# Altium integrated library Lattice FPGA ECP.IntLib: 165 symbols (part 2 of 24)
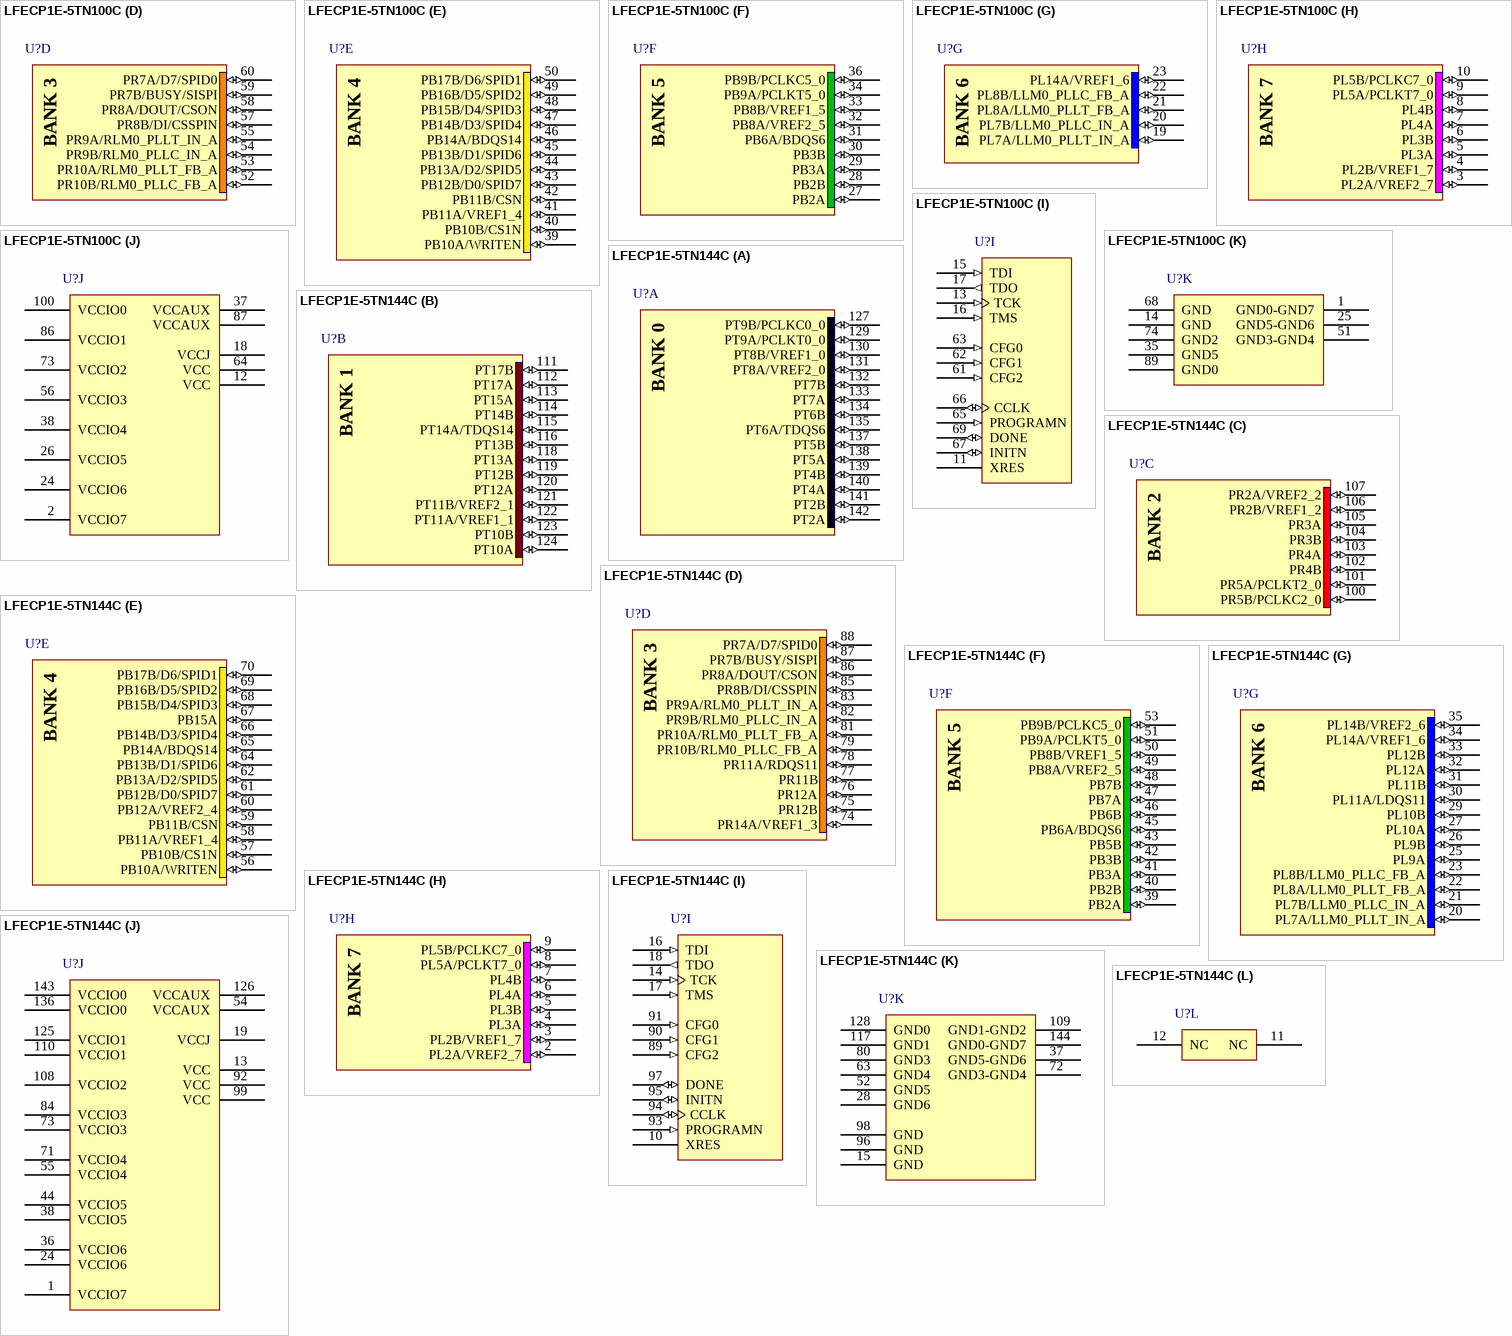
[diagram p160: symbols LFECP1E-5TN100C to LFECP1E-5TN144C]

## LFECP1E-5TN144C
designator U?
ECP 1.2V FPGA, 97 I/Os, 2 PLLs, 1.5K LUTs, 144-Pin TQFP, Pb-Free, Speed Grade 5, Commercial Temperature Grade; Note: Pins 37, 72, 109 and 144 are double bonded.; ComponentAvailability: Not Available
footprint TQFP144_N (Thin QFP, 144-Leads, Body 20x20mm, Pitch 0.5mm, IPC Medium Density)
footprint TQFP144_L (Thin QFP, 144-Leads, Body 20x20mm, Pitch 0.5mm, IPC High Density)
footprint TQFP144_M (Thin QFP, 144-Leads, Body 20x20mm, Pitch 0.5mm, IPC Low Density)
3D model ECP1E-TQFP-144 (144-Pin Thin Quad Flat Pack (TQFP144))
part A pins: 127 PT9B/PCLKC0_0 (io), 129 PT9A/PCLKT0_0 (io), 130 PT8B/VREF1_0 (io), 131 PT8A/VREF2_0 (io), 132 PT7B (io), 133 PT7A (io), 134 PT6B (io), 135 PT6A/TDQS6 (io), 137 PT5B (io), 138 PT5A (io), 139 PT4B (io), 140 PT4A (io), 141 PT2B (io), 142 PT2A (io)
part B pins: 111 PT17B (io), 112 PT17A (io), 113 PT15A (io), 114 PT14B (io), 115 PT14A/TDQS14 (io), 116 PT13B (io), 118 PT13A (io), 119 PT12B (io), 120 PT12A (io), 121 PT11B/VREF2_1 (io), 122 PT11A/VREF1_1 (io), 123 PT10B (io), 124 PT10A (io)
part C pins: 100 PR5B/PCLKC2_0 (io), 101 PR5A/PCLKT2_0 (io), 102 PR4B (io), 103 PR4A (io), 104 PR3B (io), 105 PR3A (io), 106 PR2B/VREF1_2 (io), 107 PR2A/VREF2_2 (io)
part D pins: 74 PR14A/VREF1_3 (io), 75 PR12B (io), 76 PR12A (io), 77 PR11B (io), 78 PR11A/RDQS11 (io), 79 PR10B/RLM0_PLLC_FB_A (io), 81 PR10A/RLM0_PLLT_FB_A (io), 82 PR9B/RLM0_PLLC_IN_A (io), 83 PR9A/RLM0_PLLT_IN_A (io), 85 PR8B/DI/CSSPIN (io), 86 PR8A/DOUT/CSON (io), 87 PR7B/BUSY/SISPI (io), 88 PR7A/D7/SPID0 (io)
part E pins: 56 PB10A/WRITEN (io), 57 PB10B/CS1N (io), 58 PB11A/VREF1_4 (io), 59 PB11B/CSN (io), 60 PB12A/VREF2_4 (io), 61 PB12B/D0/SPID7 (io), 62 PB13A/D2/SPID5 (io), 64 PB13B/D1/SPID6 (io), 65 PB14A/BDQS14 (io), 66 PB14B/D3/SPID4 (io), 67 PB15A (io), 68 PB15B/D4/SPID3 (io), 69 PB16B/D5/SPID2 (io), 70 PB17B/D6/SPID1 (io)
part F pins: 39 PB2A (io), 40 PB2B (io), 41 PB3A (io), 42 PB3B (io), 43 PB5B (io), 45 PB6A/BDQS6 (io), 46 PB6B (io), 47 PB7A (io), 48 PB7B (io), 49 PB8A/VREF2_5 (io), 50 PB8B/VREF1_5 (io), 51 PB9A/PCLKT5_0 (io), 53 PB9B/PCLKC5_0 (io)
part G pins: 20 PL7A/LLM0_PLLT_IN_A (io), 21 PL7B/LLM0_PLLC_IN_A (io), 22 PL8A/LLM0_PLLT_FB_A (io), 23 PL8B/LLM0_PLLC_FB_A (io), 25 PL9A (io), 26 PL9B (io), 27 PL10A (io), 29 PL10B (io), 30 PL11A/LDQS11 (io), 31 PL11B (io), 32 PL12A (io), 33 PL12B (io), 34 PL14A/VREF1_6 (io), 35 PL14B/VREF2_6 (io)
part H pins: 2 PL2A/VREF2_7 (io), 3 PL2B/VREF1_7 (io), 4 PL3A (io), 5 PL3B (io), 6 PL4A (io), 7 PL4B (io), 8 PL5A/PCLKT7_0 (io), 9 PL5B/PCLKC7_0 (io)
part I pins: 10 XRES, 14 TCK (in), 16 TDI (in), 17 TMS (in), 18 TDO (out), 89 CFG2 (in), 90 CFG1 (in), 91 CFG0 (in), 93 PROGRAMN (in), 94 CCLK (io), 95 INITN (io), 97 DONE (io)
part J pins: 1 VCCIO7 (power), 13 VCC (power), 19 VCCJ (power), 24 VCCIO6 (power), 36 VCCIO6 (power), 38 VCCIO5 (power), 44 VCCIO5 (power), 54 VCCAUX (power), 55 VCCIO4 (power), 71 VCCIO4 (power), 73 VCCIO3 (power), 84 VCCIO3 (power), 92 VCC (power), 99 VCC (power), 108 VCCIO2 (power), 110 VCCIO1 (power), 125 VCCIO1 (power), 126 VCCAUX (power), 136 VCCIO0 (power), 143 VCCIO0 (power)
part K pins: 15 GND (power), 28 GND6 (power), 37 GND5-GND6 (power), 52 GND5 (power), 63 GND4 (power), 72 GND3-GND4 (power), 80 GND3 (power), 96 GND (power), 98 GND (power), 109 GND1-GND2 (power), 117 GND1 (power), 128 GND0 (power), 144 GND0-GND7 (power)
part L pins: 11 NC, 12 NC

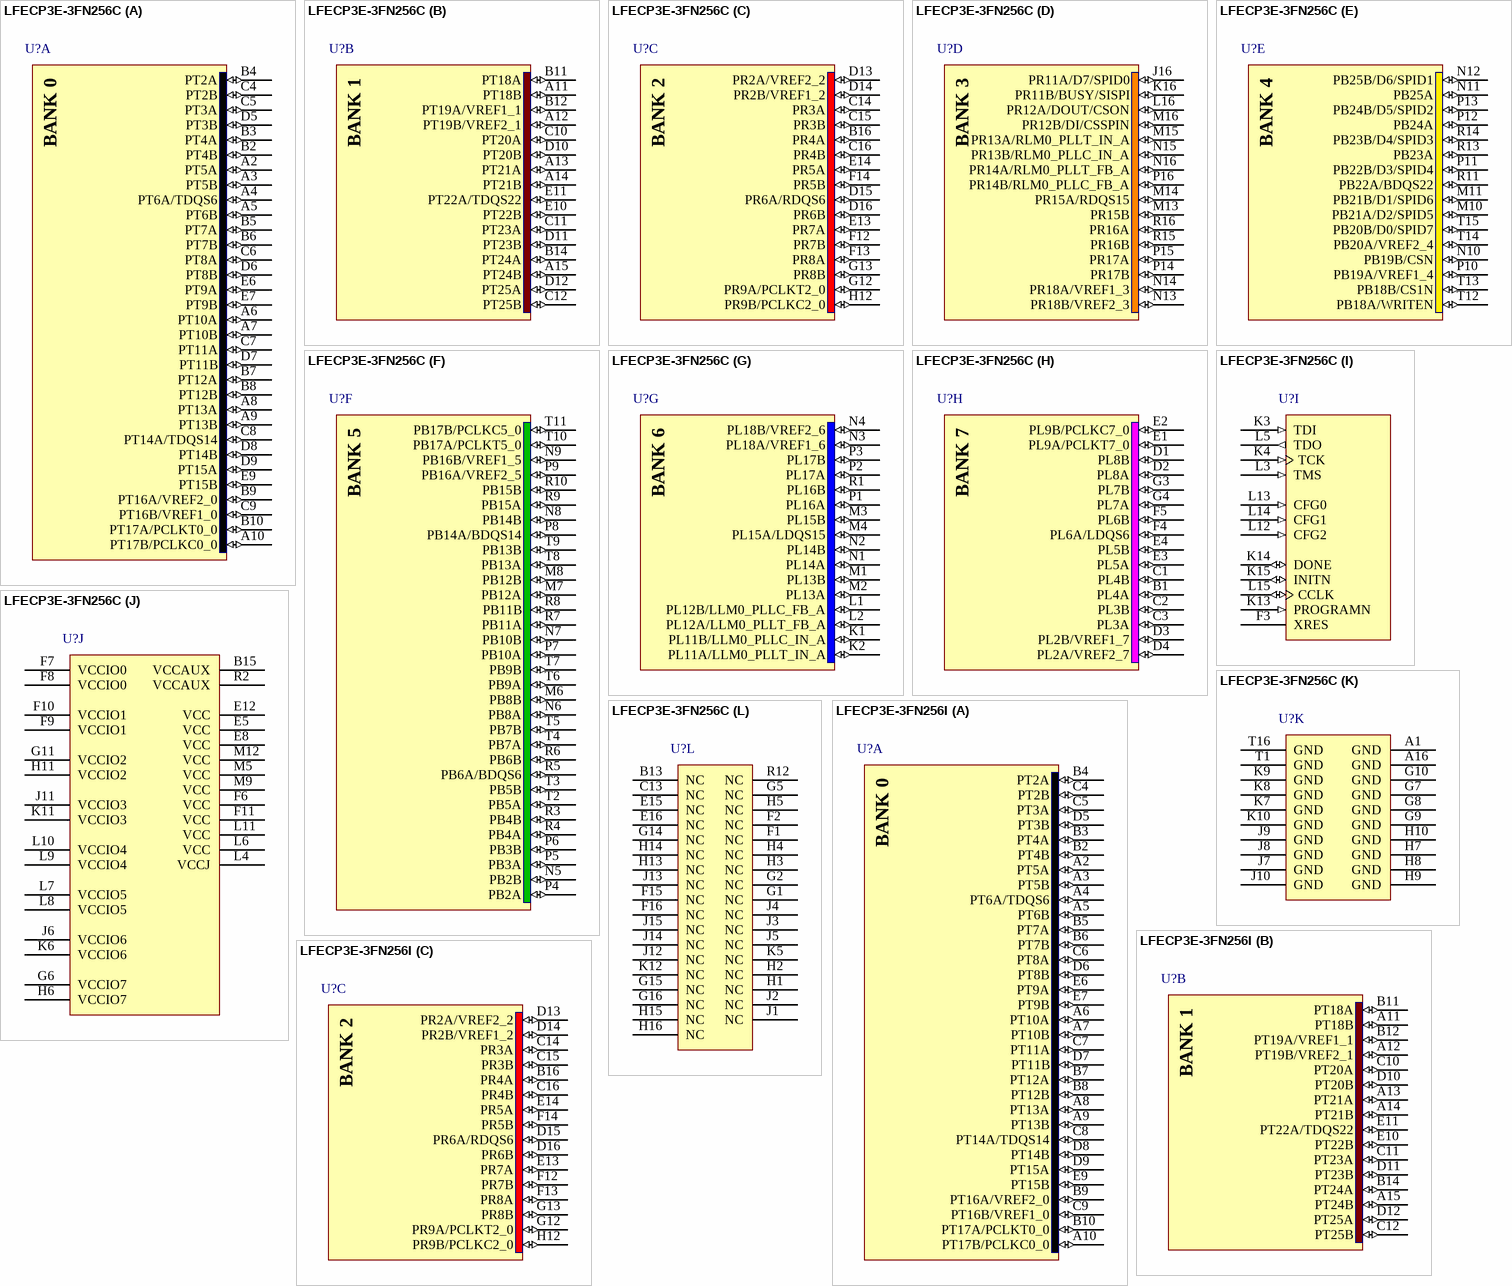
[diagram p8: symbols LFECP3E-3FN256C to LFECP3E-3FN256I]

## LFECP3E-3FN256C
designator U?
ECP 1.2V FPGA, 160 I/Os, 2 PLLs, 3.1K LUTs, 256-Pin fpBGA, Pb-Free, Speed Grade 3, Commercial Temperature Grade; ComponentAvailability: Not Available
footprint fpBGA256 (BGA, 256-Leads, Body 17x17mm, Pitch 1mm)
3D model ECP3E-fpBGA256 (256-Ball Fine Pitch Ball Grid Array (fpBGA256))
part A pins: A2 PT5A (io), A3 PT5B (io), A4 PT6A/TDQS6 (io), A5 PT6B (io), A6 PT10A (io), A7 PT10B (io), A8 PT13A (io), A9 PT13B (io), A10 PT17B/PCLKC0_0 (io), B2 PT4B (io), B3 PT4A (io), B4 PT2A (io), B5 PT7A (io), B6 PT7B (io), B7 PT12A (io), B8 PT12B (io), B9 PT16A/VREF2_0 (io), B10 PT17A/PCLKT0_0 (io), C4 PT2B (io), C5 PT3A (io), C6 PT8A (io), C7 PT11A (io), C8 PT14A/TDQS14 (io), C9 PT16B/VREF1_0 (io), D5 PT3B (io), D6 PT8B (io), D7 PT11B (io), D8 PT14B (io), D9 PT15A (io), E6 PT9A (io), E7 PT9B (io), E9 PT15B (io)
part B pins: A11 PT18B (io), A12 PT19B/VREF2_1 (io), A13 PT21A (io), A14 PT21B (io), A15 PT24B (io), B11 PT18A (io), B12 PT19A/VREF1_1 (io), B14 PT24A (io), C10 PT20A (io), C11 PT23A (io), C12 PT25B (io), D10 PT20B (io), D11 PT23B (io), D12 PT25A (io), E10 PT22B (io), E11 PT22A/TDQS22 (io)
part C pins: B16 PR4A (io), C14 PR3A (io), C15 PR3B (io), C16 PR4B (io), D13 PR2A/VREF2_2 (io), D14 PR2B/VREF1_2 (io), D15 PR6A/RDQS6 (io), D16 PR6B (io), E13 PR7A (io), E14 PR5A (io), F12 PR7B (io), F13 PR8A (io), F14 PR5B (io), G12 PR9A/PCLKT2_0 (io), G13 PR8B (io), H12 PR9B/PCLKC2_0 (io)
part D pins: J16 PR11A/D7/SPID0 (io), K16 PR11B/BUSY/SISPI (io), L16 PR12A/DOUT/CSON (io), M13 PR15B (io), M14 PR15A/RDQS15 (io), M15 PR13A/RLM0_PLLT_IN_A (io), M16 PR12B/DI/CSSPIN (io), N13 PR18B/VREF2_3 (io), N14 PR18A/VREF1_3 (io), N15 PR13B/RLM0_PLLC_IN_A (io), N16 PR14A/RLM0_PLLT_FB_A (io), P14 PR17B (io), P15 PR17A (io), P16 PR14B/RLM0_PLLC_FB_A (io), R15 PR16B (io), R16 PR16A (io)
part E pins: M10 PB21A/D2/SPID5 (io), M11 PB21B/D1/SPID6 (io), N10 PB19B/CSN (io), N11 PB25A (io), N12 PB25B/D6/SPID1 (io), P10 PB19A/VREF1_4 (io), P11 PB22B/D3/SPID4 (io), P12 PB24A (io), P13 PB24B/D5/SPID2 (io), R11 PB22A/BDQS22 (io), R13 PB23A (io), R14 PB23B/D4/SPID3 (io), T12 PB18A/WRITEN (io), T13 PB18B/CS1N (io), T14 PB20A/VREF2_4 (io), T15 PB20B/D0/SPID7 (io)
part F pins: M6 PB8B (io), M7 PB12A (io), M8 PB12B (io), N5 PB2B (io), N6 PB8A (io), N7 PB10B (io), N8 PB14B (io), N9 PB16B/VREF1_5 (io), P4 PB2A (io), P5 PB3A (io), P6 PB3B (io), P7 PB10A (io), P8 PB14A/BDQS14 (io), P9 PB16A/VREF2_5 (io), R3 PB4B (io), R4 PB4A (io), R5 PB6A/BDQS6 (io), R6 PB6B (io), R7 PB11A (io), R8 PB11B (io), R9 PB15A (io), R10 PB15B (io), T2 PB5A (io), T3 PB5B (io), T4 PB7A (io), T5 PB7B (io), T6 PB9A (io), T7 PB9B (io), T8 PB13A (io), T9 PB13B (io), T10 PB17A/PCLKT5_0 (io), T11 PB17B/PCLKC5_0 (io)
part G pins: K1 PL11B/LLM0_PLLC_IN_A (io), K2 PL11A/LLM0_PLLT_IN_A (io), L1 PL12B/LLM0_PLLC_FB_A (io), L2 PL12A/LLM0_PLLT_FB_A (io), M1 PL13B (io), M2 PL13A (io), M3 PL15B (io), M4 PL15A/LDQS15 (io), N1 PL14A (io), N2 PL14B (io), N3 PL18A/VREF1_6 (io), N4 PL18B/VREF2_6 (io), P1 PL16A (io), P2 PL17A (io), P3 PL17B (io), R1 PL16B (io)
part H pins: B1 PL4A (io), C1 PL4B (io), C2 PL3B (io), C3 PL3A (io), D1 PL8B (io), D2 PL8A (io), D3 PL2B/VREF1_7 (io), D4 PL2A/VREF2_7 (io), E1 PL9A/PCLKT7_0 (io), E2 PL9B/PCLKC7_0 (io), E3 PL5A (io), E4 PL5B (io), F4 PL6A/LDQS6 (io), F5 PL6B (io), G3 PL7B (io), G4 PL7A (io)
part I pins: F3 XRES, K3 TDI (in), K4 TCK (in), K13 PROGRAMN (in), K14 DONE (io), K15 INITN (io), L3 TMS (in), L5 TDO (out), L12 CFG2 (in), L13 CFG0 (in), L14 CFG1 (in), L15 CCLK (io)
part J pins: B15 VCCAUX (power), E5 VCC (power), E8 VCC (power), E12 VCC (power), F6 VCC (power), F7 VCCIO0 (power), F8 VCCIO0 (power), F9 VCCIO1 (power), F10 VCCIO1 (power), F11 VCC (power), G6 VCCIO7 (power), G11 VCCIO2 (power), H6 VCCIO7 (power), H11 VCCIO2 (power), J6 VCCIO6 (power), J11 VCCIO3 (power), K6 VCCIO6 (power), K11 VCCIO3 (power), L4 VCCJ (power), L6 VCC (power), L7 VCCIO5 (power), L8 VCCIO5 (power), L9 VCCIO4 (power), L10 VCCIO4 (power), L11 VCC (power), M5 VCC (power), M9 VCC (power), M12 VCC (power), R2 VCCAUX (power)
part K pins: A1 GND (power), A16 GND (power), G7 GND (power), G8 GND (power), G9 GND (power), G10 GND (power), H7 GND (power), H8 GND (power), H9 GND (power), H10 GND (power), J7 GND (power), J8 GND (power), J9 GND (power), J10 GND (power), K7 GND (power), K8 GND (power), K9 GND (power), K10 GND (power), T1 GND (power), T16 GND (power)
part L pins: B13 NC, C13 NC, E15 NC, E16 NC, F1 NC, F2 NC, F15 NC, F16 NC, G1 NC, G2 NC, G5 NC, G14 NC, G15 NC, G16 NC, H1 NC, H2 NC, H3 NC, H4 NC, H5 NC, H13 NC, H14 NC, H15 NC, H16 NC, J1 NC, J2 NC, J3 NC, J4 NC, J5 NC, J12 NC, J13 NC, J14 NC, J15 NC, K5 NC, K12 NC, R12 NC

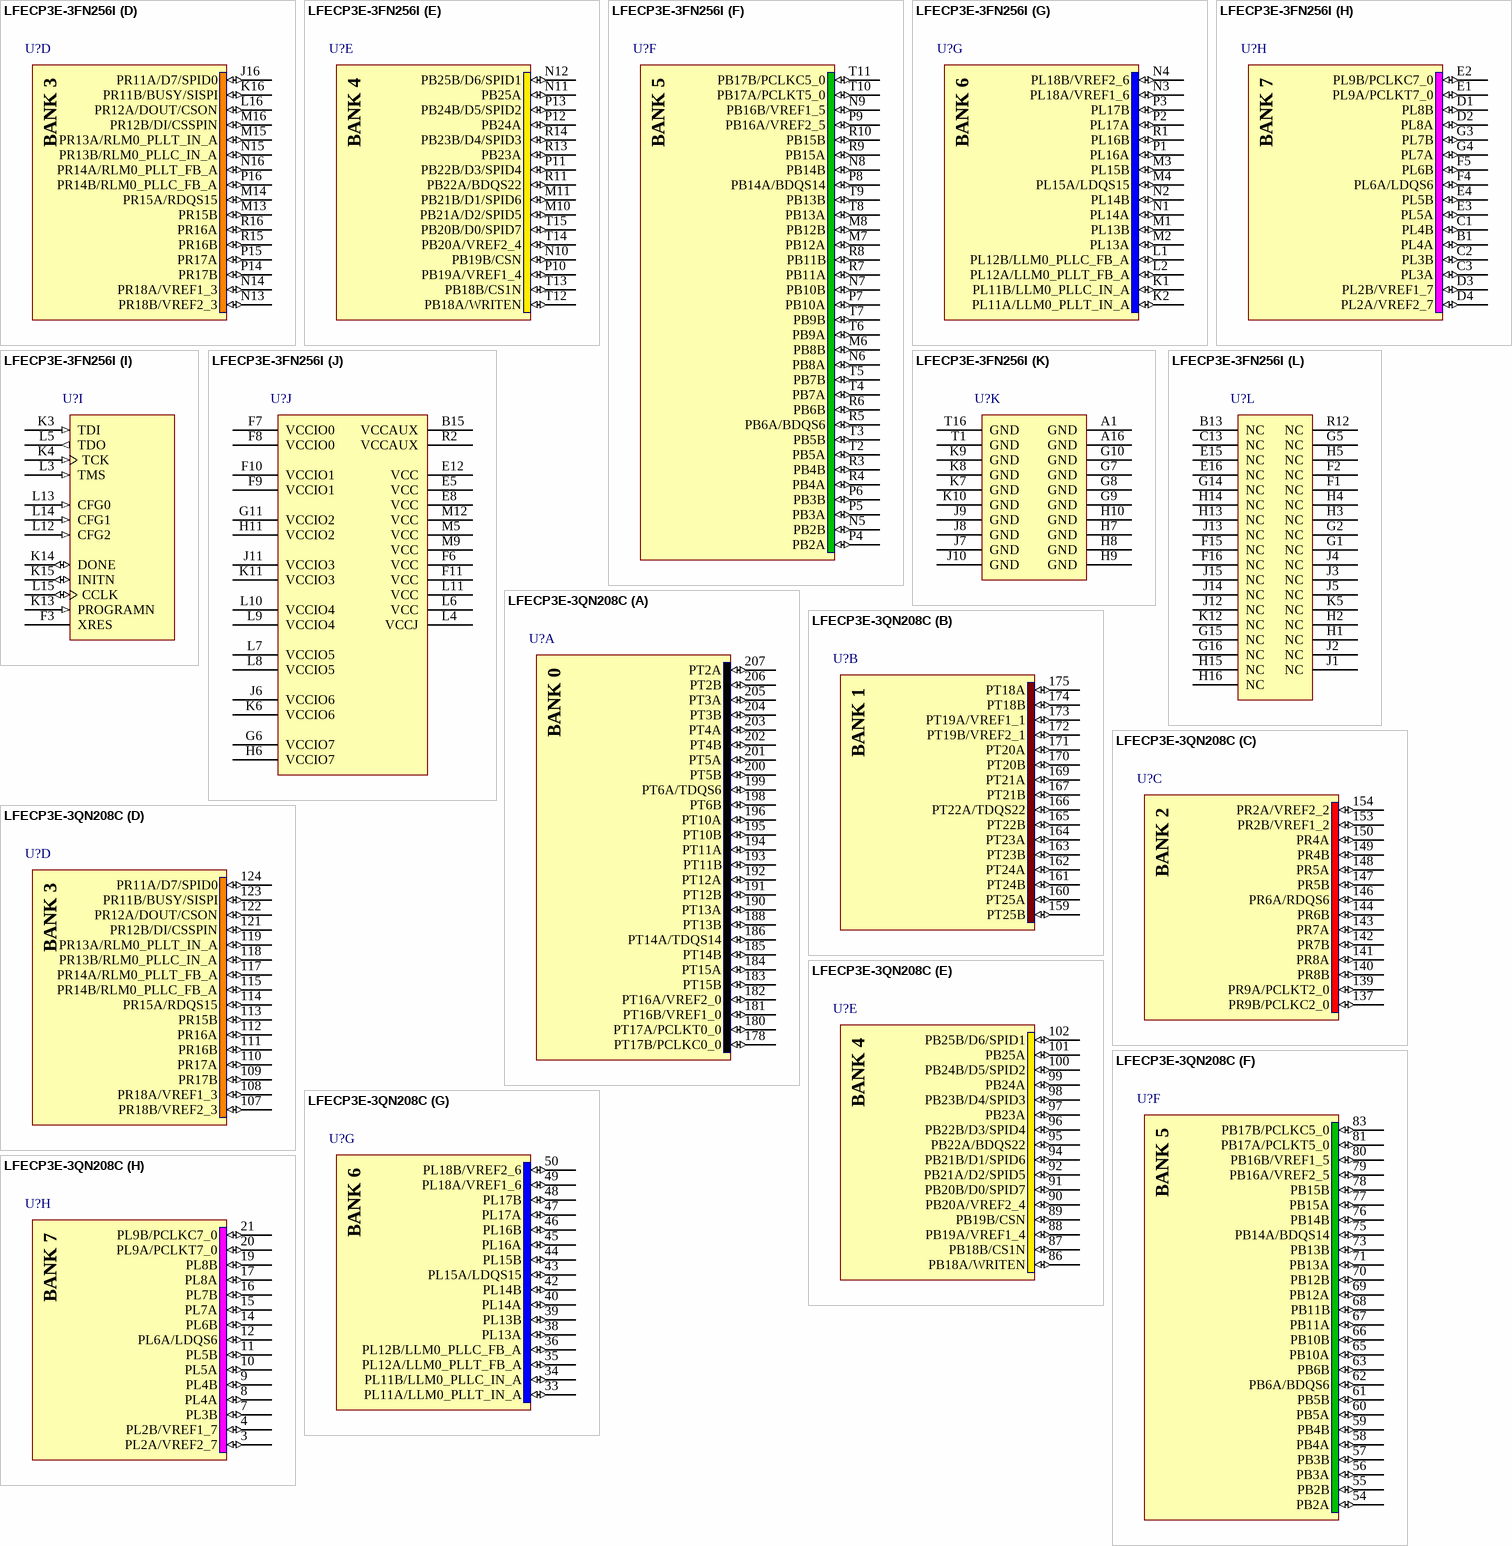
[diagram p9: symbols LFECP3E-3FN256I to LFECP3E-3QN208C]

## LFECP3E-3FN256I
designator U?
ECP 1.2V FPGA, 160 I/Os, 2 PLLs, 3.1K LUTs, 256-Pin fpBGA, Pb-Free, Speed Grade 3, Industrial Temperature Grade; ComponentAvailability: Not Available
footprint fpBGA256 (BGA, 256-Leads, Body 17x17mm, Pitch 1mm)
3D model ECP3E-fpBGA256 (256-Ball Fine Pitch Ball Grid Array (fpBGA256))
part A pins: A2 PT5A (io), A3 PT5B (io), A4 PT6A/TDQS6 (io), A5 PT6B (io), A6 PT10A (io), A7 PT10B (io), A8 PT13A (io), A9 PT13B (io), A10 PT17B/PCLKC0_0 (io), B2 PT4B (io), B3 PT4A (io), B4 PT2A (io), B5 PT7A (io), B6 PT7B (io), B7 PT12A (io), B8 PT12B (io), B9 PT16A/VREF2_0 (io), B10 PT17A/PCLKT0_0 (io), C4 PT2B (io), C5 PT3A (io), C6 PT8A (io), C7 PT11A (io), C8 PT14A/TDQS14 (io), C9 PT16B/VREF1_0 (io), D5 PT3B (io), D6 PT8B (io), D7 PT11B (io), D8 PT14B (io), D9 PT15A (io), E6 PT9A (io), E7 PT9B (io), E9 PT15B (io)
part B pins: A11 PT18B (io), A12 PT19B/VREF2_1 (io), A13 PT21A (io), A14 PT21B (io), A15 PT24B (io), B11 PT18A (io), B12 PT19A/VREF1_1 (io), B14 PT24A (io), C10 PT20A (io), C11 PT23A (io), C12 PT25B (io), D10 PT20B (io), D11 PT23B (io), D12 PT25A (io), E10 PT22B (io), E11 PT22A/TDQS22 (io)
part C pins: B16 PR4A (io), C14 PR3A (io), C15 PR3B (io), C16 PR4B (io), D13 PR2A/VREF2_2 (io), D14 PR2B/VREF1_2 (io), D15 PR6A/RDQS6 (io), D16 PR6B (io), E13 PR7A (io), E14 PR5A (io), F12 PR7B (io), F13 PR8A (io), F14 PR5B (io), G12 PR9A/PCLKT2_0 (io), G13 PR8B (io), H12 PR9B/PCLKC2_0 (io)
part D pins: J16 PR11A/D7/SPID0 (io), K16 PR11B/BUSY/SISPI (io), L16 PR12A/DOUT/CSON (io), M13 PR15B (io), M14 PR15A/RDQS15 (io), M15 PR13A/RLM0_PLLT_IN_A (io), M16 PR12B/DI/CSSPIN (io), N13 PR18B/VREF2_3 (io), N14 PR18A/VREF1_3 (io), N15 PR13B/RLM0_PLLC_IN_A (io), N16 PR14A/RLM0_PLLT_FB_A (io), P14 PR17B (io), P15 PR17A (io), P16 PR14B/RLM0_PLLC_FB_A (io), R15 PR16B (io), R16 PR16A (io)
part E pins: M10 PB21A/D2/SPID5 (io), M11 PB21B/D1/SPID6 (io), N10 PB19B/CSN (io), N11 PB25A (io), N12 PB25B/D6/SPID1 (io), P10 PB19A/VREF1_4 (io), P11 PB22B/D3/SPID4 (io), P12 PB24A (io), P13 PB24B/D5/SPID2 (io), R11 PB22A/BDQS22 (io), R13 PB23A (io), R14 PB23B/D4/SPID3 (io), T12 PB18A/WRITEN (io), T13 PB18B/CS1N (io), T14 PB20A/VREF2_4 (io), T15 PB20B/D0/SPID7 (io)
part F pins: M6 PB8B (io), M7 PB12A (io), M8 PB12B (io), N5 PB2B (io), N6 PB8A (io), N7 PB10B (io), N8 PB14B (io), N9 PB16B/VREF1_5 (io), P4 PB2A (io), P5 PB3A (io), P6 PB3B (io), P7 PB10A (io), P8 PB14A/BDQS14 (io), P9 PB16A/VREF2_5 (io), R3 PB4B (io), R4 PB4A (io), R5 PB6A/BDQS6 (io), R6 PB6B (io), R7 PB11A (io), R8 PB11B (io), R9 PB15A (io), R10 PB15B (io), T2 PB5A (io), T3 PB5B (io), T4 PB7A (io), T5 PB7B (io), T6 PB9A (io), T7 PB9B (io), T8 PB13A (io), T9 PB13B (io), T10 PB17A/PCLKT5_0 (io), T11 PB17B/PCLKC5_0 (io)
part G pins: K1 PL11B/LLM0_PLLC_IN_A (io), K2 PL11A/LLM0_PLLT_IN_A (io), L1 PL12B/LLM0_PLLC_FB_A (io), L2 PL12A/LLM0_PLLT_FB_A (io), M1 PL13B (io), M2 PL13A (io), M3 PL15B (io), M4 PL15A/LDQS15 (io), N1 PL14A (io), N2 PL14B (io), N3 PL18A/VREF1_6 (io), N4 PL18B/VREF2_6 (io), P1 PL16A (io), P2 PL17A (io), P3 PL17B (io), R1 PL16B (io)
part H pins: B1 PL4A (io), C1 PL4B (io), C2 PL3B (io), C3 PL3A (io), D1 PL8B (io), D2 PL8A (io), D3 PL2B/VREF1_7 (io), D4 PL2A/VREF2_7 (io), E1 PL9A/PCLKT7_0 (io), E2 PL9B/PCLKC7_0 (io), E3 PL5A (io), E4 PL5B (io), F4 PL6A/LDQS6 (io), F5 PL6B (io), G3 PL7B (io), G4 PL7A (io)
part I pins: F3 XRES, K3 TDI (in), K4 TCK (in), K13 PROGRAMN (in), K14 DONE (io), K15 INITN (io), L3 TMS (in), L5 TDO (out), L12 CFG2 (in), L13 CFG0 (in), L14 CFG1 (in), L15 CCLK (io)
part J pins: B15 VCCAUX (power), E5 VCC (power), E8 VCC (power), E12 VCC (power), F6 VCC (power), F7 VCCIO0 (power), F8 VCCIO0 (power), F9 VCCIO1 (power), F10 VCCIO1 (power), F11 VCC (power), G6 VCCIO7 (power), G11 VCCIO2 (power), H6 VCCIO7 (power), H11 VCCIO2 (power), J6 VCCIO6 (power), J11 VCCIO3 (power), K6 VCCIO6 (power), K11 VCCIO3 (power), L4 VCCJ (power), L6 VCC (power), L7 VCCIO5 (power), L8 VCCIO5 (power), L9 VCCIO4 (power), L10 VCCIO4 (power), L11 VCC (power), M5 VCC (power), M9 VCC (power), M12 VCC (power), R2 VCCAUX (power)
part K pins: A1 GND (power), A16 GND (power), G7 GND (power), G8 GND (power), G9 GND (power), G10 GND (power), H7 GND (power), H8 GND (power), H9 GND (power), H10 GND (power), J7 GND (power), J8 GND (power), J9 GND (power), J10 GND (power), K7 GND (power), K8 GND (power), K9 GND (power), K10 GND (power), T1 GND (power), T16 GND (power)
part L pins: B13 NC, C13 NC, E15 NC, E16 NC, F1 NC, F2 NC, F15 NC, F16 NC, G1 NC, G2 NC, G5 NC, G14 NC, G15 NC, G16 NC, H1 NC, H2 NC, H3 NC, H4 NC, H5 NC, H13 NC, H14 NC, H15 NC, H16 NC, J1 NC, J2 NC, J3 NC, J4 NC, J5 NC, J12 NC, J13 NC, J14 NC, J15 NC, K5 NC, K12 NC, R12 NC

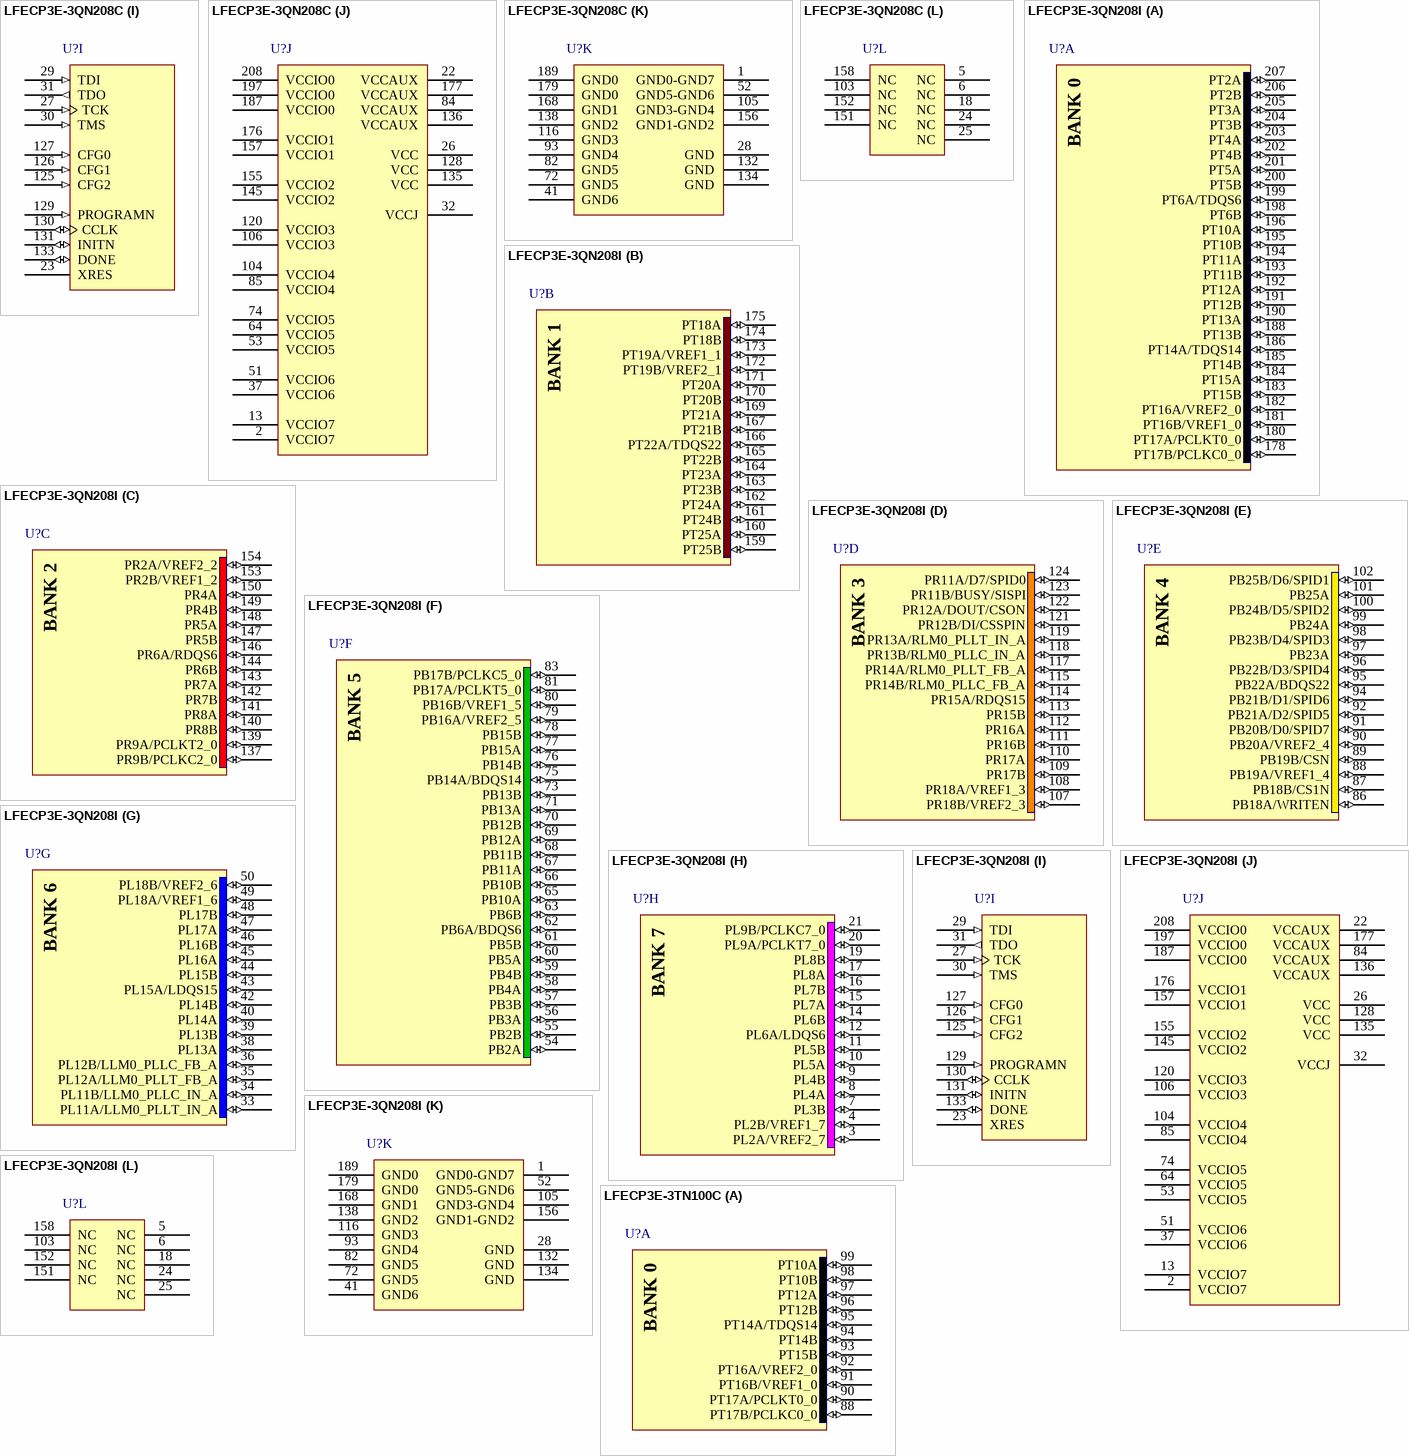
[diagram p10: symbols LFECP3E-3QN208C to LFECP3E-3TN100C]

## LFECP3E-3QN208C
designator U?
ECP 1.2V FPGA, 145 I/Os, 2 PLLs, 3.1K LUTs, 208-Pin PQFP, Pb-Free, Speed Grade 3, Commercial Temperature Grade; Note: Pins 1, 52, 105 and 156 are double bonded.; ComponentAvailability: Not Available
footprint PQFP208_N (Shrink QFP, 208-Leads, Body 28x28mm, Pitch 0.5mm, IPC Medium Density)
footprint PQFP208_L (Shrink QFP, 208-Leads, Body 28x28mm, Pitch 0.5mm, IPC High Density)
footprint PQFP208_M (Shrink QFP, 208-Leads, Body 28x28mm, Pitch 0.5mm, IPC Low Density)
3D model ECP3E-PQFP-208 (208-Pin Plastic Quad Flat Pack (PQFP208))
part A pins: 178 PT17B/PCLKC0_0 (io), 180 PT17A/PCLKT0_0 (io), 181 PT16B/VREF1_0 (io), 182 PT16A/VREF2_0 (io), 183 PT15B (io), 184 PT15A (io), 185 PT14B (io), 186 PT14A/TDQS14 (io), 188 PT13B (io), 190 PT13A (io), 191 PT12B (io), 192 PT12A (io), 193 PT11B (io), 194 PT11A (io), 195 PT10B (io), 196 PT10A (io), 198 PT6B (io), 199 PT6A/TDQS6 (io), 200 PT5B (io), 201 PT5A (io), 202 PT4B (io), 203 PT4A (io), 204 PT3B (io), 205 PT3A (io), 206 PT2B (io), 207 PT2A (io)
part B pins: 159 PT25B (io), 160 PT25A (io), 161 PT24B (io), 162 PT24A (io), 163 PT23B (io), 164 PT23A (io), 165 PT22B (io), 166 PT22A/TDQS22 (io), 167 PT21B (io), 169 PT21A (io), 170 PT20B (io), 171 PT20A (io), 172 PT19B/VREF2_1 (io), 173 PT19A/VREF1_1 (io), 174 PT18B (io), 175 PT18A (io)
part C pins: 137 PR9B/PCLKC2_0 (io), 139 PR9A/PCLKT2_0 (io), 140 PR8B (io), 141 PR8A (io), 142 PR7B (io), 143 PR7A (io), 144 PR6B (io), 146 PR6A/RDQS6 (io), 147 PR5B (io), 148 PR5A (io), 149 PR4B (io), 150 PR4A (io), 153 PR2B/VREF1_2 (io), 154 PR2A/VREF2_2 (io)
part D pins: 107 PR18B/VREF2_3 (io), 108 PR18A/VREF1_3 (io), 109 PR17B (io), 110 PR17A (io), 111 PR16B (io), 112 PR16A (io), 113 PR15B (io), 114 PR15A/RDQS15 (io), 115 PR14B/RLM0_PLLC_FB_A (io), 117 PR14A/RLM0_PLLT_FB_A (io), 118 PR13B/RLM0_PLLC_IN_A (io), 119 PR13A/RLM0_PLLT_IN_A (io), 121 PR12B/DI/CSSPIN (io), 122 PR12A/DOUT/CSON (io), 123 PR11B/BUSY/SISPI (io), 124 PR11A/D7/SPID0 (io)
part E pins: 86 PB18A/WRITEN (io), 87 PB18B/CS1N (io), 88 PB19A/VREF1_4 (io), 89 PB19B/CSN (io), 90 PB20A/VREF2_4 (io), 91 PB20B/D0/SPID7 (io), 92 PB21A/D2/SPID5 (io), 94 PB21B/D1/SPID6 (io), 95 PB22A/BDQS22 (io), 96 PB22B/D3/SPID4 (io), 97 PB23A (io), 98 PB23B/D4/SPID3 (io), 99 PB24A (io), 100 PB24B/D5/SPID2 (io), 101 PB25A (io), 102 PB25B/D6/SPID1 (io)
part F pins: 54 PB2A (io), 55 PB2B (io), 56 PB3A (io), 57 PB3B (io), 58 PB4A (io), 59 PB4B (io), 60 PB5A (io), 61 PB5B (io), 62 PB6A/BDQS6 (io), 63 PB6B (io), 65 PB10A (io), 66 PB10B (io), 67 PB11A (io), 68 PB11B (io), 69 PB12A (io), 70 PB12B (io), 71 PB13A (io), 73 PB13B (io), 75 PB14A/BDQS14 (io), 76 PB14B (io), 77 PB15A (io), 78 PB15B (io), 79 PB16A/VREF2_5 (io), 80 PB16B/VREF1_5 (io), 81 PB17A/PCLKT5_0 (io), 83 PB17B/PCLKC5_0 (io)
part G pins: 33 PL11A/LLM0_PLLT_IN_A (io), 34 PL11B/LLM0_PLLC_IN_A (io), 35 PL12A/LLM0_PLLT_FB_A (io), 36 PL12B/LLM0_PLLC_FB_A (io), 38 PL13A (io), 39 PL13B (io), 40 PL14A (io), 42 PL14B (io), 43 PL15A/LDQS15 (io), 44 PL15B (io), 45 PL16A (io), 46 PL16B (io), 47 PL17A (io), 48 PL17B (io), 49 PL18A/VREF1_6 (io), 50 PL18B/VREF2_6 (io)
part H pins: 3 PL2A/VREF2_7 (io), 4 PL2B/VREF1_7 (io), 7 PL3B (io), 8 PL4A (io), 9 PL4B (io), 10 PL5A (io), 11 PL5B (io), 12 PL6A/LDQS6 (io), 14 PL6B (io), 15 PL7A (io), 16 PL7B (io), 17 PL8A (io), 19 PL8B (io), 20 PL9A/PCLKT7_0 (io), 21 PL9B/PCLKC7_0 (io)
part I pins: 23 XRES, 27 TCK (in), 29 TDI (in), 30 TMS (in), 31 TDO (out), 125 CFG2 (in), 126 CFG1 (in), 127 CFG0 (in), 129 PROGRAMN (in), 130 CCLK (io), 131 INITN (io), 133 DONE (io)
part J pins: 2 VCCIO7 (power), 13 VCCIO7 (power), 22 VCCAUX (power), 26 VCC (power), 32 VCCJ (power), 37 VCCIO6 (power), 51 VCCIO6 (power), 53 VCCIO5 (power), 64 VCCIO5 (power), 74 VCCIO5 (power), 84 VCCAUX (power), 85 VCCIO4 (power), 104 VCCIO4 (power), 106 VCCIO3 (power), 120 VCCIO3 (power), 128 VCC (power), 135 VCC (power), 136 VCCAUX (power), 145 VCCIO2 (power), 155 VCCIO2 (power), 157 VCCIO1 (power), 176 VCCIO1 (power), 177 VCCAUX (power), 187 VCCIO0 (power), 197 VCCIO0 (power), 208 VCCIO0 (power)
part K pins: 1 GND0-GND7 (power), 28 GND (power), 41 GND6 (power), 52 GND5-GND6 (power), 72 GND5 (power), 82 GND5 (power), 93 GND4 (power), 105 GND3-GND4 (power), 116 GND3 (power), 132 GND (power), 134 GND (power), 138 GND2 (power), 156 GND1-GND2 (power), 168 GND1 (power), 179 GND0 (power), 189 GND0 (power)
part L pins: 5 NC, 6 NC, 18 NC, 24 NC, 25 NC, 103 NC, 151 NC, 152 NC, 158 NC

## LFECP3E-3QN208I
designator U?
ECP 1.2V FPGA, 145 I/Os, 2 PLLs, 3.1K LUTs, 208-Pin PQFP, Pb-Free, Speed Grade 3, Industrial Temperature Grade; Note: Pins 1, 52, 105 and 156 are double bonded.; ComponentAvailability: Not Available
footprint PQFP208_N (Shrink QFP, 208-Leads, Body 28x28mm, Pitch 0.5mm, IPC Medium Density)
footprint PQFP208_L (Shrink QFP, 208-Leads, Body 28x28mm, Pitch 0.5mm, IPC High Density)
footprint PQFP208_M (Shrink QFP, 208-Leads, Body 28x28mm, Pitch 0.5mm, IPC Low Density)
3D model ECP3E-PQFP-208 (208-Pin Plastic Quad Flat Pack (PQFP208))
part A pins: 178 PT17B/PCLKC0_0 (io), 180 PT17A/PCLKT0_0 (io), 181 PT16B/VREF1_0 (io), 182 PT16A/VREF2_0 (io), 183 PT15B (io), 184 PT15A (io), 185 PT14B (io), 186 PT14A/TDQS14 (io), 188 PT13B (io), 190 PT13A (io), 191 PT12B (io), 192 PT12A (io), 193 PT11B (io), 194 PT11A (io), 195 PT10B (io), 196 PT10A (io), 198 PT6B (io), 199 PT6A/TDQS6 (io), 200 PT5B (io), 201 PT5A (io), 202 PT4B (io), 203 PT4A (io), 204 PT3B (io), 205 PT3A (io), 206 PT2B (io), 207 PT2A (io)
part B pins: 159 PT25B (io), 160 PT25A (io), 161 PT24B (io), 162 PT24A (io), 163 PT23B (io), 164 PT23A (io), 165 PT22B (io), 166 PT22A/TDQS22 (io), 167 PT21B (io), 169 PT21A (io), 170 PT20B (io), 171 PT20A (io), 172 PT19B/VREF2_1 (io), 173 PT19A/VREF1_1 (io), 174 PT18B (io), 175 PT18A (io)
part C pins: 137 PR9B/PCLKC2_0 (io), 139 PR9A/PCLKT2_0 (io), 140 PR8B (io), 141 PR8A (io), 142 PR7B (io), 143 PR7A (io), 144 PR6B (io), 146 PR6A/RDQS6 (io), 147 PR5B (io), 148 PR5A (io), 149 PR4B (io), 150 PR4A (io), 153 PR2B/VREF1_2 (io), 154 PR2A/VREF2_2 (io)
part D pins: 107 PR18B/VREF2_3 (io), 108 PR18A/VREF1_3 (io), 109 PR17B (io), 110 PR17A (io), 111 PR16B (io), 112 PR16A (io), 113 PR15B (io), 114 PR15A/RDQS15 (io), 115 PR14B/RLM0_PLLC_FB_A (io), 117 PR14A/RLM0_PLLT_FB_A (io), 118 PR13B/RLM0_PLLC_IN_A (io), 119 PR13A/RLM0_PLLT_IN_A (io), 121 PR12B/DI/CSSPIN (io), 122 PR12A/DOUT/CSON (io), 123 PR11B/BUSY/SISPI (io), 124 PR11A/D7/SPID0 (io)
part E pins: 86 PB18A/WRITEN (io), 87 PB18B/CS1N (io), 88 PB19A/VREF1_4 (io), 89 PB19B/CSN (io), 90 PB20A/VREF2_4 (io), 91 PB20B/D0/SPID7 (io), 92 PB21A/D2/SPID5 (io), 94 PB21B/D1/SPID6 (io), 95 PB22A/BDQS22 (io), 96 PB22B/D3/SPID4 (io), 97 PB23A (io), 98 PB23B/D4/SPID3 (io), 99 PB24A (io), 100 PB24B/D5/SPID2 (io), 101 PB25A (io), 102 PB25B/D6/SPID1 (io)
part F pins: 54 PB2A (io), 55 PB2B (io), 56 PB3A (io), 57 PB3B (io), 58 PB4A (io), 59 PB4B (io), 60 PB5A (io), 61 PB5B (io), 62 PB6A/BDQS6 (io), 63 PB6B (io), 65 PB10A (io), 66 PB10B (io), 67 PB11A (io), 68 PB11B (io), 69 PB12A (io), 70 PB12B (io), 71 PB13A (io), 73 PB13B (io), 75 PB14A/BDQS14 (io), 76 PB14B (io), 77 PB15A (io), 78 PB15B (io), 79 PB16A/VREF2_5 (io), 80 PB16B/VREF1_5 (io), 81 PB17A/PCLKT5_0 (io), 83 PB17B/PCLKC5_0 (io)
part G pins: 33 PL11A/LLM0_PLLT_IN_A (io), 34 PL11B/LLM0_PLLC_IN_A (io), 35 PL12A/LLM0_PLLT_FB_A (io), 36 PL12B/LLM0_PLLC_FB_A (io), 38 PL13A (io), 39 PL13B (io), 40 PL14A (io), 42 PL14B (io), 43 PL15A/LDQS15 (io), 44 PL15B (io), 45 PL16A (io), 46 PL16B (io), 47 PL17A (io), 48 PL17B (io), 49 PL18A/VREF1_6 (io), 50 PL18B/VREF2_6 (io)
part H pins: 3 PL2A/VREF2_7 (io), 4 PL2B/VREF1_7 (io), 7 PL3B (io), 8 PL4A (io), 9 PL4B (io), 10 PL5A (io), 11 PL5B (io), 12 PL6A/LDQS6 (io), 14 PL6B (io), 15 PL7A (io), 16 PL7B (io), 17 PL8A (io), 19 PL8B (io), 20 PL9A/PCLKT7_0 (io), 21 PL9B/PCLKC7_0 (io)
part I pins: 23 XRES, 27 TCK (in), 29 TDI (in), 30 TMS (in), 31 TDO (out), 125 CFG2 (in), 126 CFG1 (in), 127 CFG0 (in), 129 PROGRAMN (in), 130 CCLK (io), 131 INITN (io), 133 DONE (io)
part J pins: 2 VCCIO7 (power), 13 VCCIO7 (power), 22 VCCAUX (power), 26 VCC (power), 32 VCCJ (power), 37 VCCIO6 (power), 51 VCCIO6 (power), 53 VCCIO5 (power), 64 VCCIO5 (power), 74 VCCIO5 (power), 84 VCCAUX (power), 85 VCCIO4 (power), 104 VCCIO4 (power), 106 VCCIO3 (power), 120 VCCIO3 (power), 128 VCC (power), 135 VCC (power), 136 VCCAUX (power), 145 VCCIO2 (power), 155 VCCIO2 (power), 157 VCCIO1 (power), 176 VCCIO1 (power), 177 VCCAUX (power), 187 VCCIO0 (power), 197 VCCIO0 (power), 208 VCCIO0 (power)
part K pins: 1 GND0-GND7 (power), 28 GND (power), 41 GND6 (power), 52 GND5-GND6 (power), 72 GND5 (power), 82 GND5 (power), 93 GND4 (power), 105 GND3-GND4 (power), 116 GND3 (power), 132 GND (power), 134 GND (power), 138 GND2 (power), 156 GND1-GND2 (power), 168 GND1 (power), 179 GND0 (power), 189 GND0 (power)
part L pins: 5 NC, 6 NC, 18 NC, 24 NC, 25 NC, 103 NC, 151 NC, 152 NC, 158 NC

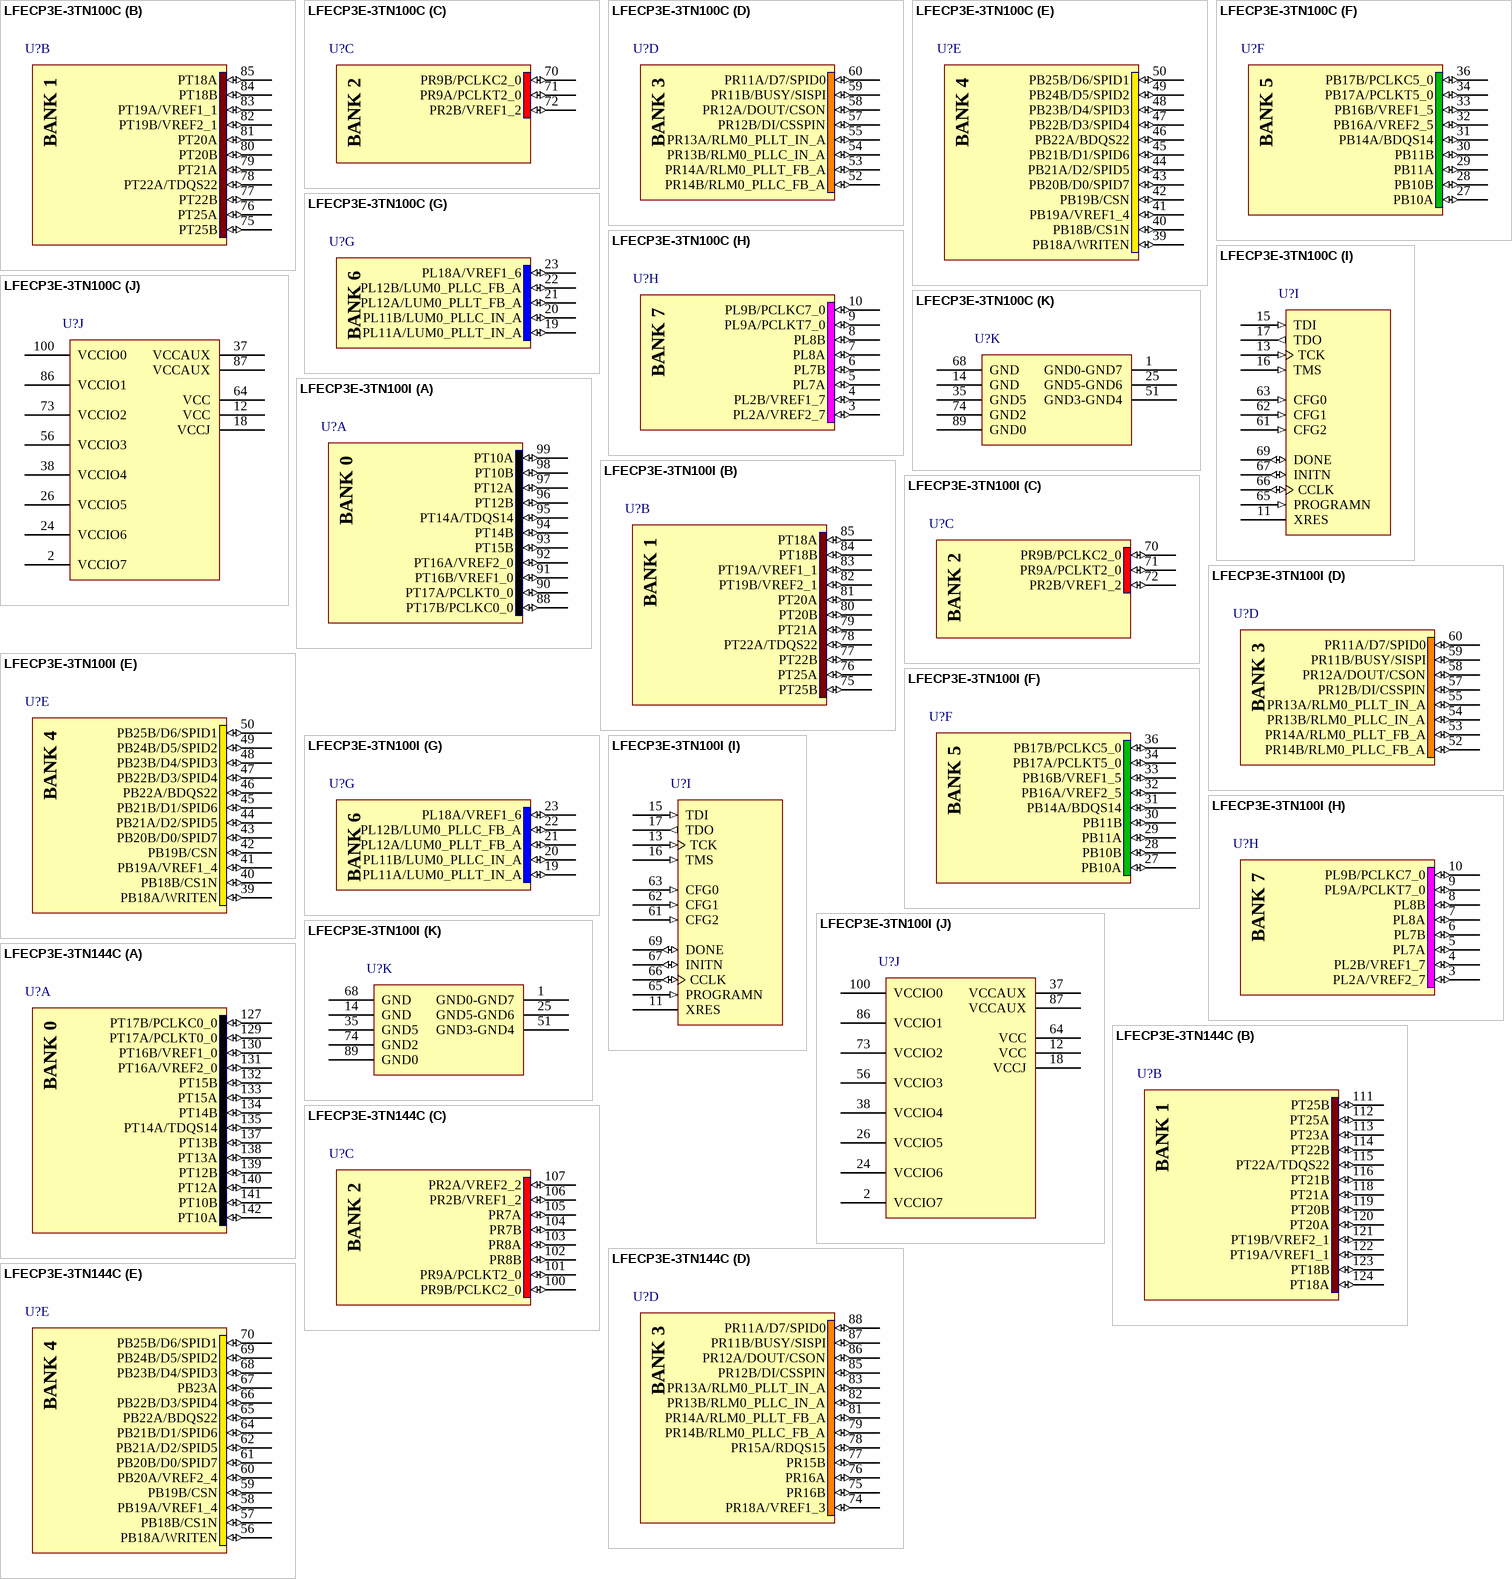
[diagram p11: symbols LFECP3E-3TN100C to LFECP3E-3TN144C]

## LFECP3E-3TN100C
designator U?
ECP 1.2V FPGA, 67 I/Os, 2 PLLs, 3.1K LUTs, 100-Pin TQFP, Pb-Free, Speed Grade 3, Commercial Temperature Grade; Note: Pins 1, 25 and 51 are double bonded.; ComponentAvailability: Not Available
footprint TQFP100_N (Thin QFP, 100-Leads, Body 14x14mm, Pitch 0.5mm, IPC Medium Density)
footprint TQFP100_L (Thin QFP, 100-Leads, Body 14x14mm, Pitch 0.5mm, IPC High Density)
footprint TQFP100_M (Thin QFP, 100-Leads, Body 14x14mm, Pitch 0.5mm, IPC Low Density)
3D model ECP3E-TQFP-100 (100-Pin Thin Quad Flat Pack (TQFP100))
part A pins: 88 PT17B/PCLKC0_0 (io), 90 PT17A/PCLKT0_0 (io), 91 PT16B/VREF1_0 (io), 92 PT16A/VREF2_0 (io), 93 PT15B (io), 94 PT14B (io), 95 PT14A/TDQS14 (io), 96 PT12B (io), 97 PT12A (io), 98 PT10B (io), 99 PT10A (io)
part B pins: 75 PT25B (io), 76 PT25A (io), 77 PT22B (io), 78 PT22A/TDQS22 (io), 79 PT21A (io), 80 PT20B (io), 81 PT20A (io), 82 PT19B/VREF2_1 (io), 83 PT19A/VREF1_1 (io), 84 PT18B (io), 85 PT18A (io)
part C pins: 70 PR9B/PCLKC2_0 (io), 71 PR9A/PCLKT2_0 (io), 72 PR2B/VREF1_2 (io)
part D pins: 52 PR14B/RLM0_PLLC_FB_A (io), 53 PR14A/RLM0_PLLT_FB_A (io), 54 PR13B/RLM0_PLLC_IN_A (io), 55 PR13A/RLM0_PLLT_IN_A (io), 57 PR12B/DI/CSSPIN (io), 58 PR12A/DOUT/CSON (io), 59 PR11B/BUSY/SISPI (io), 60 PR11A/D7/SPID0 (io)
part E pins: 39 PB18A/WRITEN (io), 40 PB18B/CS1N (io), 41 PB19A/VREF1_4 (io), 42 PB19B/CSN (io), 43 PB20B/D0/SPID7 (io), 44 PB21A/D2/SPID5 (io), 45 PB21B/D1/SPID6 (io), 46 PB22A/BDQS22 (io), 47 PB22B/D3/SPID4 (io), 48 PB23B/D4/SPID3 (io), 49 PB24B/D5/SPID2 (io), 50 PB25B/D6/SPID1 (io)
part F pins: 27 PB10A (io), 28 PB10B (io), 29 PB11A (io), 30 PB11B (io), 31 PB14A/BDQS14 (io), 32 PB16A/VREF2_5 (io), 33 PB16B/VREF1_5 (io), 34 PB17A/PCLKT5_0 (io), 36 PB17B/PCLKC5_0 (io)
part G pins: 19 PL11A/LUM0_PLLT_IN_A (io), 20 PL11B/LUM0_PLLC_IN_A (io), 21 PL12A/LUM0_PLLT_FB_A (io), 22 PL12B/LUM0_PLLC_FB_A (io), 23 PL18A/VREF1_6 (io)
part H pins: 3 PL2A/VREF2_7 (io), 4 PL2B/VREF1_7 (io), 5 PL7A (io), 6 PL7B (io), 7 PL8A (io), 8 PL8B (io), 9 PL9A/PCLKT7_0 (io), 10 PL9B/PCLKC7_0 (io)
part I pins: 11 XRES, 13 TCK (in), 15 TDI (in), 16 TMS (in), 17 TDO (out), 61 CFG2 (in), 62 CFG1 (in), 63 CFG0 (in), 65 PROGRAMN (in), 66 CCLK (io), 67 INITN (io), 69 DONE (io)
part J pins: 2 VCCIO7 (power), 12 VCC (power), 18 VCCJ (power), 24 VCCIO6 (power), 26 VCCIO5 (power), 37 VCCAUX (power), 38 VCCIO4 (power), 56 VCCIO3 (power), 64 VCC (power), 73 VCCIO2 (power), 86 VCCIO1 (power), 87 VCCAUX (power), 100 VCCIO0 (power)
part K pins: 1 GND0-GND7 (power), 14 GND (power), 25 GND5-GND6 (power), 35 GND5 (power), 51 GND3-GND4 (power), 68 GND (power), 74 GND2 (power), 89 GND0 (power)

## LFECP3E-3TN100I
designator U?
ECP 1.2V FPGA, 67 I/Os, 2 PLLs, 3.1K LUTs, 100-Pin TQFP, Pb-Free, Speed Grade 3, Industrial Temperature Grade; Note: Pins 1, 25 and 51 are double bonded.; ComponentAvailability: Not Available
footprint TQFP100_N (Thin QFP, 100-Leads, Body 14x14mm, Pitch 0.5mm, IPC Medium Density)
footprint TQFP100_L (Thin QFP, 100-Leads, Body 14x14mm, Pitch 0.5mm, IPC High Density)
footprint TQFP100_M (Thin QFP, 100-Leads, Body 14x14mm, Pitch 0.5mm, IPC Low Density)
3D model ECP3E-TQFP-100 (100-Pin Thin Quad Flat Pack (TQFP100))
part A pins: 88 PT17B/PCLKC0_0 (io), 90 PT17A/PCLKT0_0 (io), 91 PT16B/VREF1_0 (io), 92 PT16A/VREF2_0 (io), 93 PT15B (io), 94 PT14B (io), 95 PT14A/TDQS14 (io), 96 PT12B (io), 97 PT12A (io), 98 PT10B (io), 99 PT10A (io)
part B pins: 75 PT25B (io), 76 PT25A (io), 77 PT22B (io), 78 PT22A/TDQS22 (io), 79 PT21A (io), 80 PT20B (io), 81 PT20A (io), 82 PT19B/VREF2_1 (io), 83 PT19A/VREF1_1 (io), 84 PT18B (io), 85 PT18A (io)
part C pins: 70 PR9B/PCLKC2_0 (io), 71 PR9A/PCLKT2_0 (io), 72 PR2B/VREF1_2 (io)
part D pins: 52 PR14B/RLM0_PLLC_FB_A (io), 53 PR14A/RLM0_PLLT_FB_A (io), 54 PR13B/RLM0_PLLC_IN_A (io), 55 PR13A/RLM0_PLLT_IN_A (io), 57 PR12B/DI/CSSPIN (io), 58 PR12A/DOUT/CSON (io), 59 PR11B/BUSY/SISPI (io), 60 PR11A/D7/SPID0 (io)
part E pins: 39 PB18A/WRITEN (io), 40 PB18B/CS1N (io), 41 PB19A/VREF1_4 (io), 42 PB19B/CSN (io), 43 PB20B/D0/SPID7 (io), 44 PB21A/D2/SPID5 (io), 45 PB21B/D1/SPID6 (io), 46 PB22A/BDQS22 (io), 47 PB22B/D3/SPID4 (io), 48 PB23B/D4/SPID3 (io), 49 PB24B/D5/SPID2 (io), 50 PB25B/D6/SPID1 (io)
part F pins: 27 PB10A (io), 28 PB10B (io), 29 PB11A (io), 30 PB11B (io), 31 PB14A/BDQS14 (io), 32 PB16A/VREF2_5 (io), 33 PB16B/VREF1_5 (io), 34 PB17A/PCLKT5_0 (io), 36 PB17B/PCLKC5_0 (io)
part G pins: 19 PL11A/LUM0_PLLT_IN_A (io), 20 PL11B/LUM0_PLLC_IN_A (io), 21 PL12A/LUM0_PLLT_FB_A (io), 22 PL12B/LUM0_PLLC_FB_A (io), 23 PL18A/VREF1_6 (io)
part H pins: 3 PL2A/VREF2_7 (io), 4 PL2B/VREF1_7 (io), 5 PL7A (io), 6 PL7B (io), 7 PL8A (io), 8 PL8B (io), 9 PL9A/PCLKT7_0 (io), 10 PL9B/PCLKC7_0 (io)
part I pins: 11 XRES, 13 TCK (in), 15 TDI (in), 16 TMS (in), 17 TDO (out), 61 CFG2 (in), 62 CFG1 (in), 63 CFG0 (in), 65 PROGRAMN (in), 66 CCLK (io), 67 INITN (io), 69 DONE (io)
part J pins: 2 VCCIO7 (power), 12 VCC (power), 18 VCCJ (power), 24 VCCIO6 (power), 26 VCCIO5 (power), 37 VCCAUX (power), 38 VCCIO4 (power), 56 VCCIO3 (power), 64 VCC (power), 73 VCCIO2 (power), 86 VCCIO1 (power), 87 VCCAUX (power), 100 VCCIO0 (power)
part K pins: 1 GND0-GND7 (power), 14 GND (power), 25 GND5-GND6 (power), 35 GND5 (power), 51 GND3-GND4 (power), 68 GND (power), 74 GND2 (power), 89 GND0 (power)

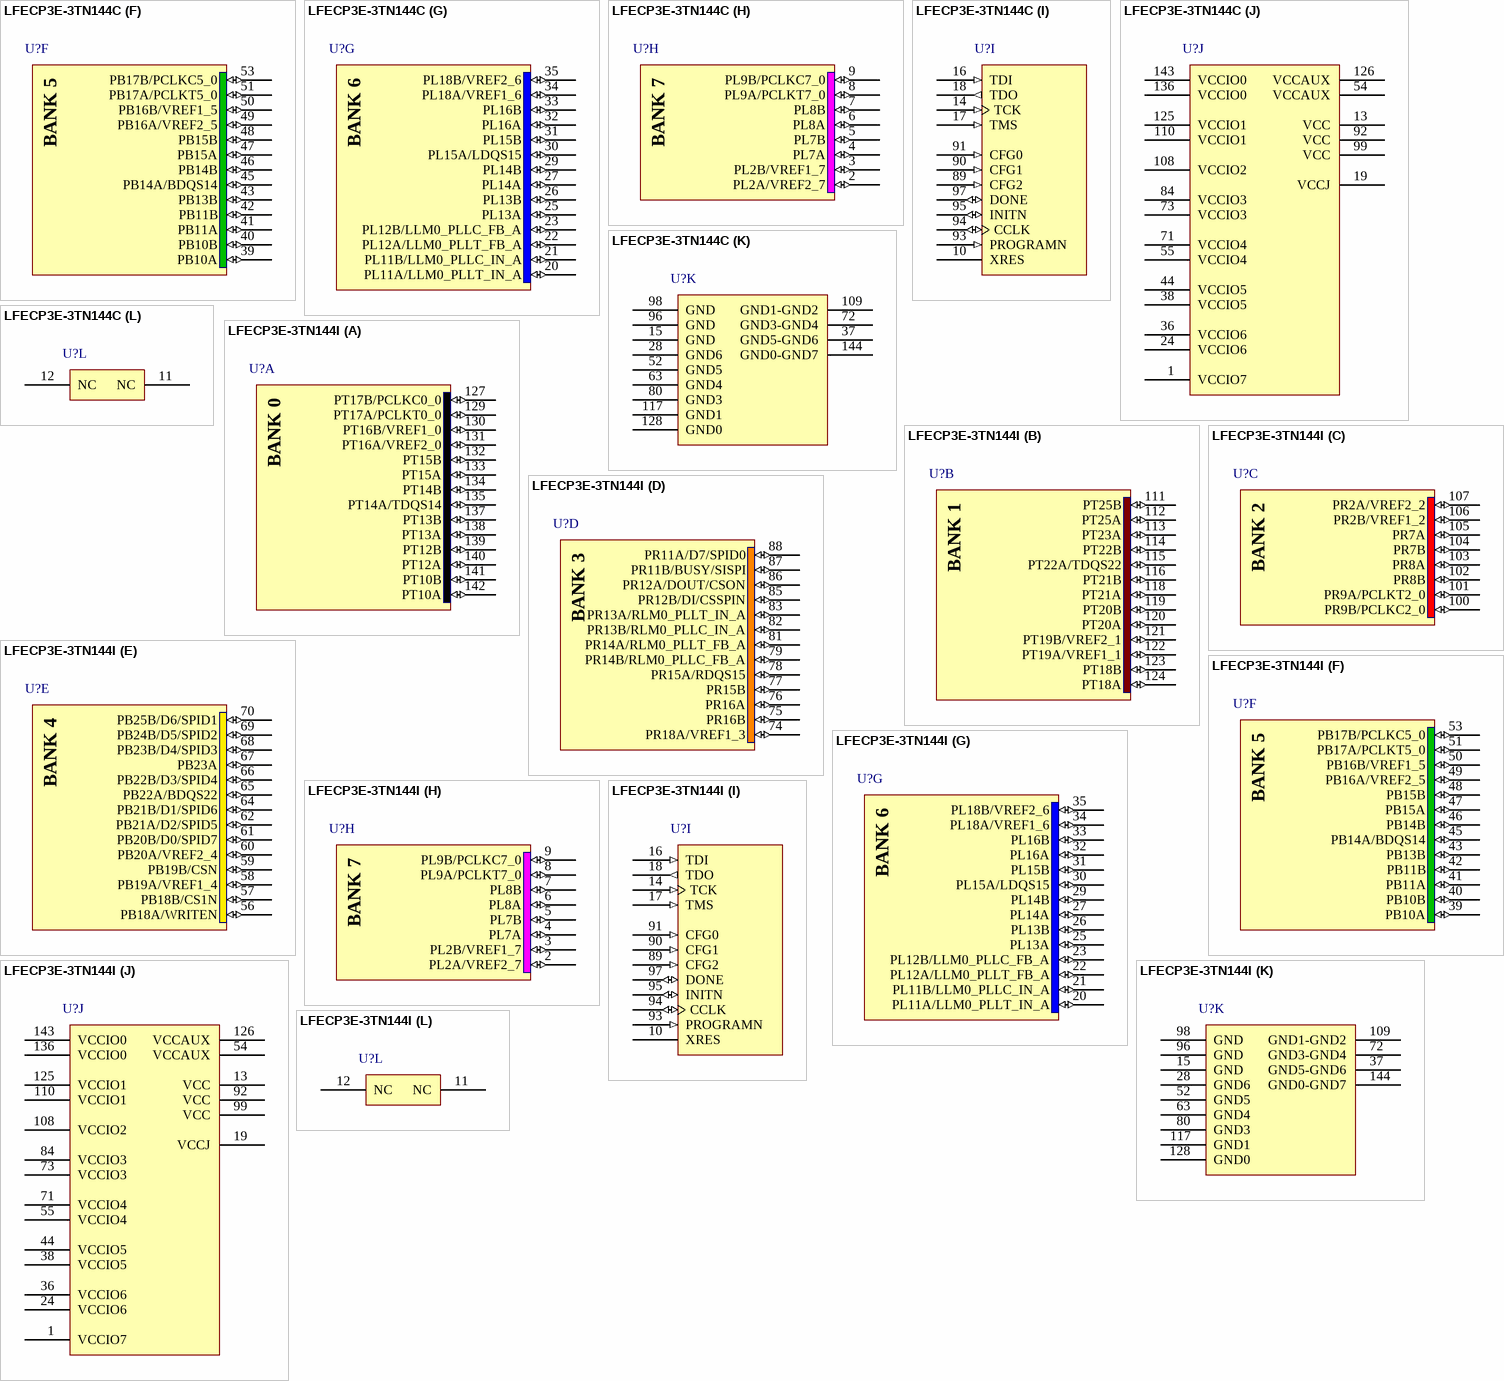
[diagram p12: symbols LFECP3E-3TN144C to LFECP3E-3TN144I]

## LFECP3E-3TN144C
designator U?
ECP 1.2V FPGA, 97 I/Os, 2 PLLs, 3.1K LUTs, 144-Pin TQFP, Pb-Free, Speed Grade 3, Commercial Temperature Grade; Note: Pins 37, 72, 109 and 144 are double bonded.; ComponentAvailability: Not Available
footprint TQFP144_N (Thin QFP, 144-Leads, Body 20x20mm, Pitch 0.5mm, IPC Medium Density)
footprint TQFP144_L (Thin QFP, 144-Leads, Body 20x20mm, Pitch 0.5mm, IPC High Density)
footprint TQFP144_M (Thin QFP, 144-Leads, Body 20x20mm, Pitch 0.5mm, IPC Low Density)
3D model ECP3E-TQFP-144 (144-Pin Thin Quad Flat Pack (TQFP144))
part A pins: 127 PT17B/PCLKC0_0 (io), 129 PT17A/PCLKT0_0 (io), 130 PT16B/VREF1_0 (io), 131 PT16A/VREF2_0 (io), 132 PT15B (io), 133 PT15A (io), 134 PT14B (io), 135 PT14A/TDQS14 (io), 137 PT13B (io), 138 PT13A (io), 139 PT12B (io), 140 PT12A (io), 141 PT10B (io), 142 PT10A (io)
part B pins: 111 PT25B (io), 112 PT25A (io), 113 PT23A (io), 114 PT22B (io), 115 PT22A/TDQS22 (io), 116 PT21B (io), 118 PT21A (io), 119 PT20B (io), 120 PT20A (io), 121 PT19B/VREF2_1 (io), 122 PT19A/VREF1_1 (io), 123 PT18B (io), 124 PT18A (io)
part C pins: 100 PR9B/PCLKC2_0 (io), 101 PR9A/PCLKT2_0 (io), 102 PR8B (io), 103 PR8A (io), 104 PR7B (io), 105 PR7A (io), 106 PR2B/VREF1_2 (io), 107 PR2A/VREF2_2 (io)
part D pins: 74 PR18A/VREF1_3 (io), 75 PR16B (io), 76 PR16A (io), 77 PR15B (io), 78 PR15A/RDQS15 (io), 79 PR14B/RLM0_PLLC_FB_A (io), 81 PR14A/RLM0_PLLT_FB_A (io), 82 PR13B/RLM0_PLLC_IN_A (io), 83 PR13A/RLM0_PLLT_IN_A (io), 85 PR12B/DI/CSSPIN (io), 86 PR12A/DOUT/CSON (io), 87 PR11B/BUSY/SISPI (io), 88 PR11A/D7/SPID0 (io)
part E pins: 56 PB18A/WRITEN (io), 57 PB18B/CS1N (io), 58 PB19A/VREF1_4 (io), 59 PB19B/CSN (io), 60 PB20A/VREF2_4 (io), 61 PB20B/D0/SPID7 (io), 62 PB21A/D2/SPID5 (io), 64 PB21B/D1/SPID6 (io), 65 PB22A/BDQS22 (io), 66 PB22B/D3/SPID4 (io), 67 PB23A (io), 68 PB23B/D4/SPID3 (io), 69 PB24B/D5/SPID2 (io), 70 PB25B/D6/SPID1 (io)
part F pins: 39 PB10A (io), 40 PB10B (io), 41 PB11A (io), 42 PB11B (io), 43 PB13B (io), 45 PB14A/BDQS14 (io), 46 PB14B (io), 47 PB15A (io), 48 PB15B (io), 49 PB16A/VREF2_5 (io), 50 PB16B/VREF1_5 (io), 51 PB17A/PCLKT5_0 (io), 53 PB17B/PCLKC5_0 (io)
part G pins: 20 PL11A/LLM0_PLLT_IN_A (io), 21 PL11B/LLM0_PLLC_IN_A (io), 22 PL12A/LLM0_PLLT_FB_A (io), 23 PL12B/LLM0_PLLC_FB_A (io), 25 PL13A (io), 26 PL13B (io), 27 PL14A (io), 29 PL14B (io), 30 PL15A/LDQS15 (io), 31 PL15B (io), 32 PL16A (io), 33 PL16B (io), 34 PL18A/VREF1_6 (io), 35 PL18B/VREF2_6 (io)
part H pins: 2 PL2A/VREF2_7 (io), 3 PL2B/VREF1_7 (io), 4 PL7A (io), 5 PL7B (io), 6 PL8A (io), 7 PL8B (io), 8 PL9A/PCLKT7_0 (io), 9 PL9B/PCLKC7_0 (io)
part I pins: 10 XRES, 14 TCK (in), 16 TDI (in), 17 TMS (in), 18 TDO (out), 89 CFG2 (in), 90 CFG1 (in), 91 CFG0 (in), 93 PROGRAMN (in), 94 CCLK (io), 95 INITN (io), 97 DONE (io)
part J pins: 1 VCCIO7 (power), 13 VCC (power), 19 VCCJ (power), 24 VCCIO6 (power), 36 VCCIO6 (power), 38 VCCIO5 (power), 44 VCCIO5 (power), 54 VCCAUX (power), 55 VCCIO4 (power), 71 VCCIO4 (power), 73 VCCIO3 (power), 84 VCCIO3 (power), 92 VCC (power), 99 VCC (power), 108 VCCIO2 (power), 110 VCCIO1 (power), 125 VCCIO1 (power), 126 VCCAUX (power), 136 VCCIO0 (power), 143 VCCIO0 (power)
part K pins: 15 GND (power), 28 GND6 (power), 37 GND5-GND6 (power), 52 GND5 (power), 63 GND4 (power), 72 GND3-GND4 (power), 80 GND3 (power), 96 GND (power), 98 GND (power), 109 GND1-GND2 (power), 117 GND1 (power), 128 GND0 (power), 144 GND0-GND7 (power)
part L pins: 11 NC, 12 NC

## LFECP3E-3TN144I
designator U?
ECP 1.2V FPGA, 97 I/Os, 2 PLLs, 3.1K LUTs, 144-Pin TQFP, Pb-Free, Speed Grade 3, Industrial Temperature Grade; Note: Pins 37, 72, 109 and 144 are double bonded.; ComponentAvailability: Not Available
footprint TQFP144_N (Thin QFP, 144-Leads, Body 20x20mm, Pitch 0.5mm, IPC Medium Density)
footprint TQFP144_L (Thin QFP, 144-Leads, Body 20x20mm, Pitch 0.5mm, IPC High Density)
footprint TQFP144_M (Thin QFP, 144-Leads, Body 20x20mm, Pitch 0.5mm, IPC Low Density)
3D model ECP3E-TQFP-144 (144-Pin Thin Quad Flat Pack (TQFP144))
part A pins: 127 PT17B/PCLKC0_0 (io), 129 PT17A/PCLKT0_0 (io), 130 PT16B/VREF1_0 (io), 131 PT16A/VREF2_0 (io), 132 PT15B (io), 133 PT15A (io), 134 PT14B (io), 135 PT14A/TDQS14 (io), 137 PT13B (io), 138 PT13A (io), 139 PT12B (io), 140 PT12A (io), 141 PT10B (io), 142 PT10A (io)
part B pins: 111 PT25B (io), 112 PT25A (io), 113 PT23A (io), 114 PT22B (io), 115 PT22A/TDQS22 (io), 116 PT21B (io), 118 PT21A (io), 119 PT20B (io), 120 PT20A (io), 121 PT19B/VREF2_1 (io), 122 PT19A/VREF1_1 (io), 123 PT18B (io), 124 PT18A (io)
part C pins: 100 PR9B/PCLKC2_0 (io), 101 PR9A/PCLKT2_0 (io), 102 PR8B (io), 103 PR8A (io), 104 PR7B (io), 105 PR7A (io), 106 PR2B/VREF1_2 (io), 107 PR2A/VREF2_2 (io)
part D pins: 74 PR18A/VREF1_3 (io), 75 PR16B (io), 76 PR16A (io), 77 PR15B (io), 78 PR15A/RDQS15 (io), 79 PR14B/RLM0_PLLC_FB_A (io), 81 PR14A/RLM0_PLLT_FB_A (io), 82 PR13B/RLM0_PLLC_IN_A (io), 83 PR13A/RLM0_PLLT_IN_A (io), 85 PR12B/DI/CSSPIN (io), 86 PR12A/DOUT/CSON (io), 87 PR11B/BUSY/SISPI (io), 88 PR11A/D7/SPID0 (io)
part E pins: 56 PB18A/WRITEN (io), 57 PB18B/CS1N (io), 58 PB19A/VREF1_4 (io), 59 PB19B/CSN (io), 60 PB20A/VREF2_4 (io), 61 PB20B/D0/SPID7 (io), 62 PB21A/D2/SPID5 (io), 64 PB21B/D1/SPID6 (io), 65 PB22A/BDQS22 (io), 66 PB22B/D3/SPID4 (io), 67 PB23A (io), 68 PB23B/D4/SPID3 (io), 69 PB24B/D5/SPID2 (io), 70 PB25B/D6/SPID1 (io)
part F pins: 39 PB10A (io), 40 PB10B (io), 41 PB11A (io), 42 PB11B (io), 43 PB13B (io), 45 PB14A/BDQS14 (io), 46 PB14B (io), 47 PB15A (io), 48 PB15B (io), 49 PB16A/VREF2_5 (io), 50 PB16B/VREF1_5 (io), 51 PB17A/PCLKT5_0 (io), 53 PB17B/PCLKC5_0 (io)
part G pins: 20 PL11A/LLM0_PLLT_IN_A (io), 21 PL11B/LLM0_PLLC_IN_A (io), 22 PL12A/LLM0_PLLT_FB_A (io), 23 PL12B/LLM0_PLLC_FB_A (io), 25 PL13A (io), 26 PL13B (io), 27 PL14A (io), 29 PL14B (io), 30 PL15A/LDQS15 (io), 31 PL15B (io), 32 PL16A (io), 33 PL16B (io), 34 PL18A/VREF1_6 (io), 35 PL18B/VREF2_6 (io)
part H pins: 2 PL2A/VREF2_7 (io), 3 PL2B/VREF1_7 (io), 4 PL7A (io), 5 PL7B (io), 6 PL8A (io), 7 PL8B (io), 8 PL9A/PCLKT7_0 (io), 9 PL9B/PCLKC7_0 (io)
part I pins: 10 XRES, 14 TCK (in), 16 TDI (in), 17 TMS (in), 18 TDO (out), 89 CFG2 (in), 90 CFG1 (in), 91 CFG0 (in), 93 PROGRAMN (in), 94 CCLK (io), 95 INITN (io), 97 DONE (io)
part J pins: 1 VCCIO7 (power), 13 VCC (power), 19 VCCJ (power), 24 VCCIO6 (power), 36 VCCIO6 (power), 38 VCCIO5 (power), 44 VCCIO5 (power), 54 VCCAUX (power), 55 VCCIO4 (power), 71 VCCIO4 (power), 73 VCCIO3 (power), 84 VCCIO3 (power), 92 VCC (power), 99 VCC (power), 108 VCCIO2 (power), 110 VCCIO1 (power), 125 VCCIO1 (power), 126 VCCAUX (power), 136 VCCIO0 (power), 143 VCCIO0 (power)
part K pins: 15 GND (power), 28 GND6 (power), 37 GND5-GND6 (power), 52 GND5 (power), 63 GND4 (power), 72 GND3-GND4 (power), 80 GND3 (power), 96 GND (power), 98 GND (power), 109 GND1-GND2 (power), 117 GND1 (power), 128 GND0 (power), 144 GND0-GND7 (power)
part L pins: 11 NC, 12 NC

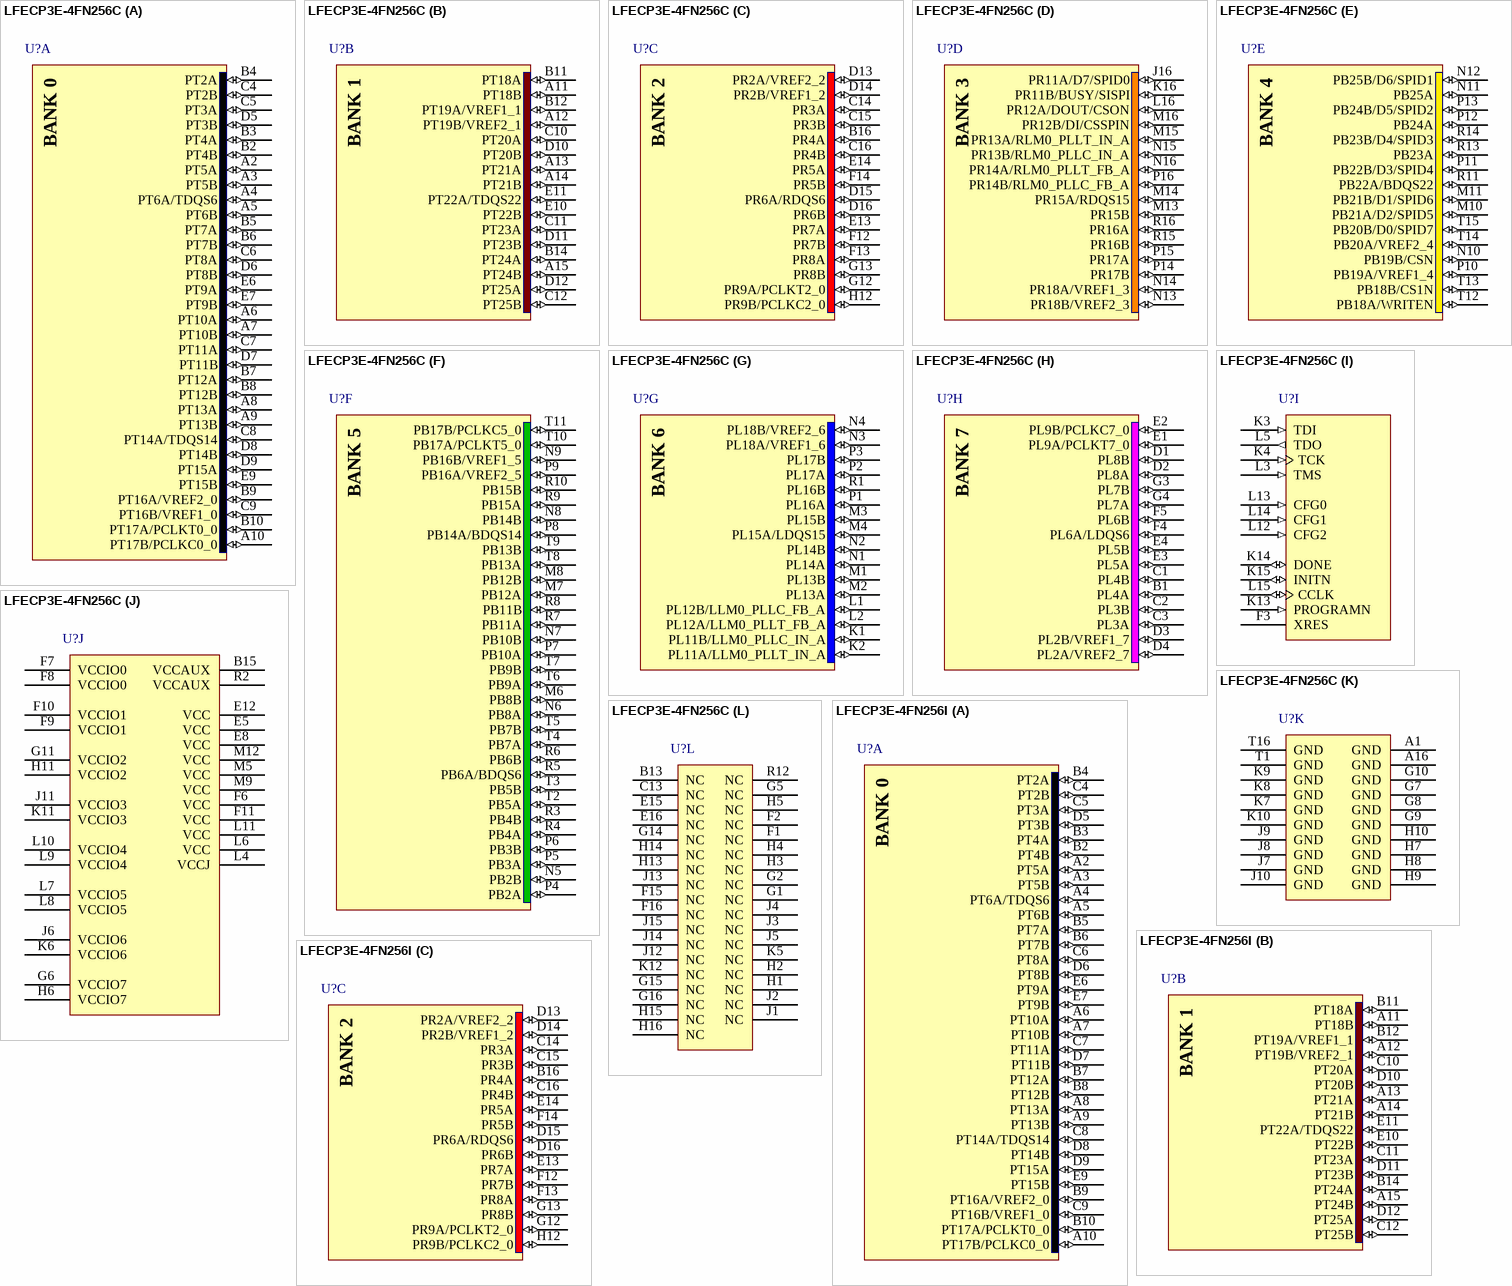
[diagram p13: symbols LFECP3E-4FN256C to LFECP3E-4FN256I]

## LFECP3E-4FN256C
designator U?
ECP 1.2V FPGA, 160 I/Os, 2 PLLs, 3.1K LUTs, 256-Pin fpBGA, Pb-Free, Speed Grade 4, Commercial Temperature Grade; ComponentAvailability: Not Available
footprint fpBGA256 (BGA, 256-Leads, Body 17x17mm, Pitch 1mm)
3D model ECP3E-fpBGA256 (256-Ball Fine Pitch Ball Grid Array (fpBGA256))
part A pins: A2 PT5A (io), A3 PT5B (io), A4 PT6A/TDQS6 (io), A5 PT6B (io), A6 PT10A (io), A7 PT10B (io), A8 PT13A (io), A9 PT13B (io), A10 PT17B/PCLKC0_0 (io), B2 PT4B (io), B3 PT4A (io), B4 PT2A (io), B5 PT7A (io), B6 PT7B (io), B7 PT12A (io), B8 PT12B (io), B9 PT16A/VREF2_0 (io), B10 PT17A/PCLKT0_0 (io), C4 PT2B (io), C5 PT3A (io), C6 PT8A (io), C7 PT11A (io), C8 PT14A/TDQS14 (io), C9 PT16B/VREF1_0 (io), D5 PT3B (io), D6 PT8B (io), D7 PT11B (io), D8 PT14B (io), D9 PT15A (io), E6 PT9A (io), E7 PT9B (io), E9 PT15B (io)
part B pins: A11 PT18B (io), A12 PT19B/VREF2_1 (io), A13 PT21A (io), A14 PT21B (io), A15 PT24B (io), B11 PT18A (io), B12 PT19A/VREF1_1 (io), B14 PT24A (io), C10 PT20A (io), C11 PT23A (io), C12 PT25B (io), D10 PT20B (io), D11 PT23B (io), D12 PT25A (io), E10 PT22B (io), E11 PT22A/TDQS22 (io)
part C pins: B16 PR4A (io), C14 PR3A (io), C15 PR3B (io), C16 PR4B (io), D13 PR2A/VREF2_2 (io), D14 PR2B/VREF1_2 (io), D15 PR6A/RDQS6 (io), D16 PR6B (io), E13 PR7A (io), E14 PR5A (io), F12 PR7B (io), F13 PR8A (io), F14 PR5B (io), G12 PR9A/PCLKT2_0 (io), G13 PR8B (io), H12 PR9B/PCLKC2_0 (io)
part D pins: J16 PR11A/D7/SPID0 (io), K16 PR11B/BUSY/SISPI (io), L16 PR12A/DOUT/CSON (io), M13 PR15B (io), M14 PR15A/RDQS15 (io), M15 PR13A/RLM0_PLLT_IN_A (io), M16 PR12B/DI/CSSPIN (io), N13 PR18B/VREF2_3 (io), N14 PR18A/VREF1_3 (io), N15 PR13B/RLM0_PLLC_IN_A (io), N16 PR14A/RLM0_PLLT_FB_A (io), P14 PR17B (io), P15 PR17A (io), P16 PR14B/RLM0_PLLC_FB_A (io), R15 PR16B (io), R16 PR16A (io)
part E pins: M10 PB21A/D2/SPID5 (io), M11 PB21B/D1/SPID6 (io), N10 PB19B/CSN (io), N11 PB25A (io), N12 PB25B/D6/SPID1 (io), P10 PB19A/VREF1_4 (io), P11 PB22B/D3/SPID4 (io), P12 PB24A (io), P13 PB24B/D5/SPID2 (io), R11 PB22A/BDQS22 (io), R13 PB23A (io), R14 PB23B/D4/SPID3 (io), T12 PB18A/WRITEN (io), T13 PB18B/CS1N (io), T14 PB20A/VREF2_4 (io), T15 PB20B/D0/SPID7 (io)
part F pins: M6 PB8B (io), M7 PB12A (io), M8 PB12B (io), N5 PB2B (io), N6 PB8A (io), N7 PB10B (io), N8 PB14B (io), N9 PB16B/VREF1_5 (io), P4 PB2A (io), P5 PB3A (io), P6 PB3B (io), P7 PB10A (io), P8 PB14A/BDQS14 (io), P9 PB16A/VREF2_5 (io), R3 PB4B (io), R4 PB4A (io), R5 PB6A/BDQS6 (io), R6 PB6B (io), R7 PB11A (io), R8 PB11B (io), R9 PB15A (io), R10 PB15B (io), T2 PB5A (io), T3 PB5B (io), T4 PB7A (io), T5 PB7B (io), T6 PB9A (io), T7 PB9B (io), T8 PB13A (io), T9 PB13B (io), T10 PB17A/PCLKT5_0 (io), T11 PB17B/PCLKC5_0 (io)
part G pins: K1 PL11B/LLM0_PLLC_IN_A (io), K2 PL11A/LLM0_PLLT_IN_A (io), L1 PL12B/LLM0_PLLC_FB_A (io), L2 PL12A/LLM0_PLLT_FB_A (io), M1 PL13B (io), M2 PL13A (io), M3 PL15B (io), M4 PL15A/LDQS15 (io), N1 PL14A (io), N2 PL14B (io), N3 PL18A/VREF1_6 (io), N4 PL18B/VREF2_6 (io), P1 PL16A (io), P2 PL17A (io), P3 PL17B (io), R1 PL16B (io)
part H pins: B1 PL4A (io), C1 PL4B (io), C2 PL3B (io), C3 PL3A (io), D1 PL8B (io), D2 PL8A (io), D3 PL2B/VREF1_7 (io), D4 PL2A/VREF2_7 (io), E1 PL9A/PCLKT7_0 (io), E2 PL9B/PCLKC7_0 (io), E3 PL5A (io), E4 PL5B (io), F4 PL6A/LDQS6 (io), F5 PL6B (io), G3 PL7B (io), G4 PL7A (io)
part I pins: F3 XRES, K3 TDI (in), K4 TCK (in), K13 PROGRAMN (in), K14 DONE (io), K15 INITN (io), L3 TMS (in), L5 TDO (out), L12 CFG2 (in), L13 CFG0 (in), L14 CFG1 (in), L15 CCLK (io)
part J pins: B15 VCCAUX (power), E5 VCC (power), E8 VCC (power), E12 VCC (power), F6 VCC (power), F7 VCCIO0 (power), F8 VCCIO0 (power), F9 VCCIO1 (power), F10 VCCIO1 (power), F11 VCC (power), G6 VCCIO7 (power), G11 VCCIO2 (power), H6 VCCIO7 (power), H11 VCCIO2 (power), J6 VCCIO6 (power), J11 VCCIO3 (power), K6 VCCIO6 (power), K11 VCCIO3 (power), L4 VCCJ (power), L6 VCC (power), L7 VCCIO5 (power), L8 VCCIO5 (power), L9 VCCIO4 (power), L10 VCCIO4 (power), L11 VCC (power), M5 VCC (power), M9 VCC (power), M12 VCC (power), R2 VCCAUX (power)
part K pins: A1 GND (power), A16 GND (power), G7 GND (power), G8 GND (power), G9 GND (power), G10 GND (power), H7 GND (power), H8 GND (power), H9 GND (power), H10 GND (power), J7 GND (power), J8 GND (power), J9 GND (power), J10 GND (power), K7 GND (power), K8 GND (power), K9 GND (power), K10 GND (power), T1 GND (power), T16 GND (power)
part L pins: B13 NC, C13 NC, E15 NC, E16 NC, F1 NC, F2 NC, F15 NC, F16 NC, G1 NC, G2 NC, G5 NC, G14 NC, G15 NC, G16 NC, H1 NC, H2 NC, H3 NC, H4 NC, H5 NC, H13 NC, H14 NC, H15 NC, H16 NC, J1 NC, J2 NC, J3 NC, J4 NC, J5 NC, J12 NC, J13 NC, J14 NC, J15 NC, K5 NC, K12 NC, R12 NC

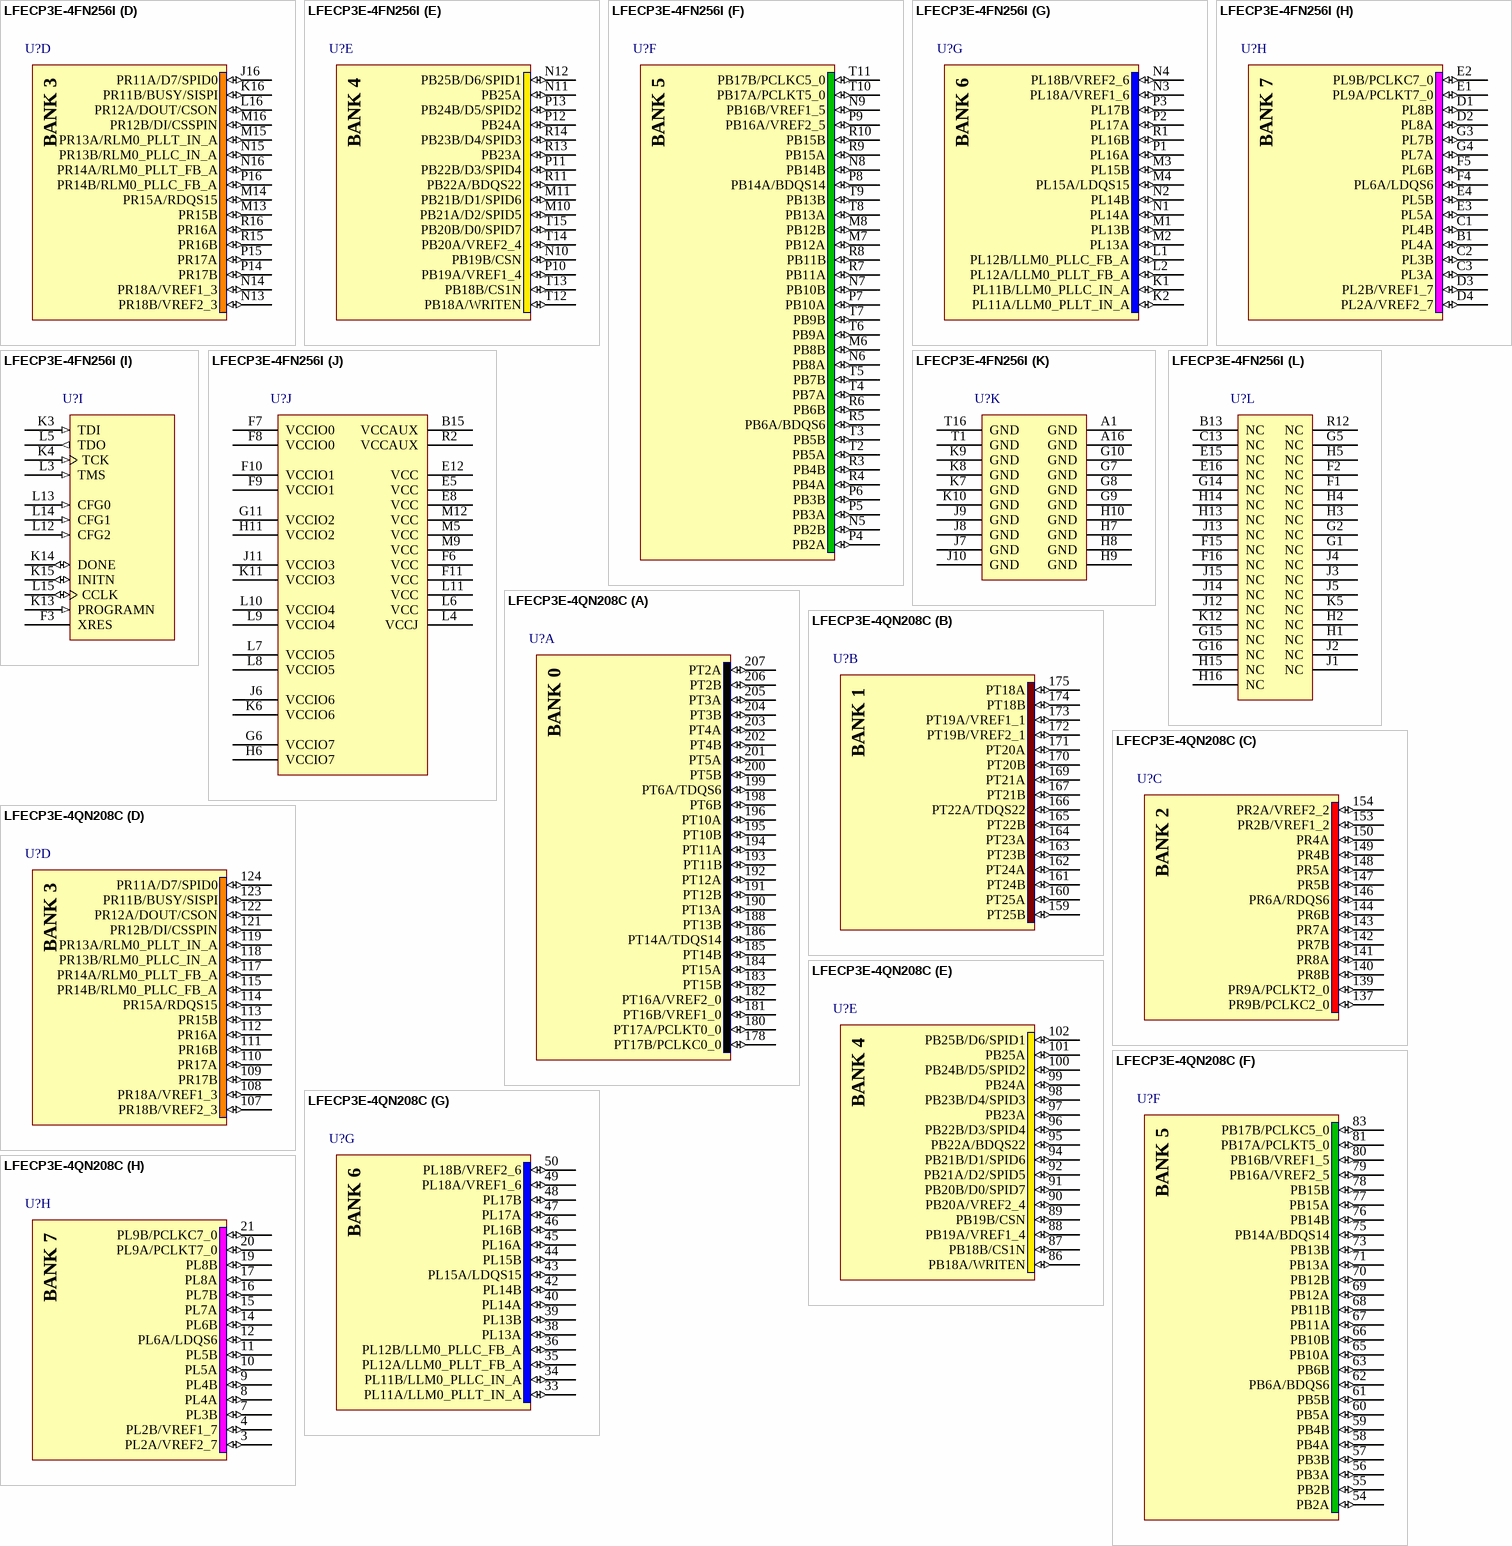
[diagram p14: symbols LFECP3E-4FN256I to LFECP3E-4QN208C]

## LFECP3E-4FN256I
designator U?
ECP 1.2V FPGA, 160 I/Os, 2 PLLs, 3.1K LUTs, 256-Pin fpBGA, Pb-Free, Speed Grade 4, Industrial Temperature Grade; ComponentAvailability: Not Available
footprint fpBGA256 (BGA, 256-Leads, Body 17x17mm, Pitch 1mm)
3D model ECP3E-fpBGA256 (256-Ball Fine Pitch Ball Grid Array (fpBGA256))
part A pins: A2 PT5A (io), A3 PT5B (io), A4 PT6A/TDQS6 (io), A5 PT6B (io), A6 PT10A (io), A7 PT10B (io), A8 PT13A (io), A9 PT13B (io), A10 PT17B/PCLKC0_0 (io), B2 PT4B (io), B3 PT4A (io), B4 PT2A (io), B5 PT7A (io), B6 PT7B (io), B7 PT12A (io), B8 PT12B (io), B9 PT16A/VREF2_0 (io), B10 PT17A/PCLKT0_0 (io), C4 PT2B (io), C5 PT3A (io), C6 PT8A (io), C7 PT11A (io), C8 PT14A/TDQS14 (io), C9 PT16B/VREF1_0 (io), D5 PT3B (io), D6 PT8B (io), D7 PT11B (io), D8 PT14B (io), D9 PT15A (io), E6 PT9A (io), E7 PT9B (io), E9 PT15B (io)
part B pins: A11 PT18B (io), A12 PT19B/VREF2_1 (io), A13 PT21A (io), A14 PT21B (io), A15 PT24B (io), B11 PT18A (io), B12 PT19A/VREF1_1 (io), B14 PT24A (io), C10 PT20A (io), C11 PT23A (io), C12 PT25B (io), D10 PT20B (io), D11 PT23B (io), D12 PT25A (io), E10 PT22B (io), E11 PT22A/TDQS22 (io)
part C pins: B16 PR4A (io), C14 PR3A (io), C15 PR3B (io), C16 PR4B (io), D13 PR2A/VREF2_2 (io), D14 PR2B/VREF1_2 (io), D15 PR6A/RDQS6 (io), D16 PR6B (io), E13 PR7A (io), E14 PR5A (io), F12 PR7B (io), F13 PR8A (io), F14 PR5B (io), G12 PR9A/PCLKT2_0 (io), G13 PR8B (io), H12 PR9B/PCLKC2_0 (io)
part D pins: J16 PR11A/D7/SPID0 (io), K16 PR11B/BUSY/SISPI (io), L16 PR12A/DOUT/CSON (io), M13 PR15B (io), M14 PR15A/RDQS15 (io), M15 PR13A/RLM0_PLLT_IN_A (io), M16 PR12B/DI/CSSPIN (io), N13 PR18B/VREF2_3 (io), N14 PR18A/VREF1_3 (io), N15 PR13B/RLM0_PLLC_IN_A (io), N16 PR14A/RLM0_PLLT_FB_A (io), P14 PR17B (io), P15 PR17A (io), P16 PR14B/RLM0_PLLC_FB_A (io), R15 PR16B (io), R16 PR16A (io)
part E pins: M10 PB21A/D2/SPID5 (io), M11 PB21B/D1/SPID6 (io), N10 PB19B/CSN (io), N11 PB25A (io), N12 PB25B/D6/SPID1 (io), P10 PB19A/VREF1_4 (io), P11 PB22B/D3/SPID4 (io), P12 PB24A (io), P13 PB24B/D5/SPID2 (io), R11 PB22A/BDQS22 (io), R13 PB23A (io), R14 PB23B/D4/SPID3 (io), T12 PB18A/WRITEN (io), T13 PB18B/CS1N (io), T14 PB20A/VREF2_4 (io), T15 PB20B/D0/SPID7 (io)
part F pins: M6 PB8B (io), M7 PB12A (io), M8 PB12B (io), N5 PB2B (io), N6 PB8A (io), N7 PB10B (io), N8 PB14B (io), N9 PB16B/VREF1_5 (io), P4 PB2A (io), P5 PB3A (io), P6 PB3B (io), P7 PB10A (io), P8 PB14A/BDQS14 (io), P9 PB16A/VREF2_5 (io), R3 PB4B (io), R4 PB4A (io), R5 PB6A/BDQS6 (io), R6 PB6B (io), R7 PB11A (io), R8 PB11B (io), R9 PB15A (io), R10 PB15B (io), T2 PB5A (io), T3 PB5B (io), T4 PB7A (io), T5 PB7B (io), T6 PB9A (io), T7 PB9B (io), T8 PB13A (io), T9 PB13B (io), T10 PB17A/PCLKT5_0 (io), T11 PB17B/PCLKC5_0 (io)
part G pins: K1 PL11B/LLM0_PLLC_IN_A (io), K2 PL11A/LLM0_PLLT_IN_A (io), L1 PL12B/LLM0_PLLC_FB_A (io), L2 PL12A/LLM0_PLLT_FB_A (io), M1 PL13B (io), M2 PL13A (io), M3 PL15B (io), M4 PL15A/LDQS15 (io), N1 PL14A (io), N2 PL14B (io), N3 PL18A/VREF1_6 (io), N4 PL18B/VREF2_6 (io), P1 PL16A (io), P2 PL17A (io), P3 PL17B (io), R1 PL16B (io)
part H pins: B1 PL4A (io), C1 PL4B (io), C2 PL3B (io), C3 PL3A (io), D1 PL8B (io), D2 PL8A (io), D3 PL2B/VREF1_7 (io), D4 PL2A/VREF2_7 (io), E1 PL9A/PCLKT7_0 (io), E2 PL9B/PCLKC7_0 (io), E3 PL5A (io), E4 PL5B (io), F4 PL6A/LDQS6 (io), F5 PL6B (io), G3 PL7B (io), G4 PL7A (io)
part I pins: F3 XRES, K3 TDI (in), K4 TCK (in), K13 PROGRAMN (in), K14 DONE (io), K15 INITN (io), L3 TMS (in), L5 TDO (out), L12 CFG2 (in), L13 CFG0 (in), L14 CFG1 (in), L15 CCLK (io)
part J pins: B15 VCCAUX (power), E5 VCC (power), E8 VCC (power), E12 VCC (power), F6 VCC (power), F7 VCCIO0 (power), F8 VCCIO0 (power), F9 VCCIO1 (power), F10 VCCIO1 (power), F11 VCC (power), G6 VCCIO7 (power), G11 VCCIO2 (power), H6 VCCIO7 (power), H11 VCCIO2 (power), J6 VCCIO6 (power), J11 VCCIO3 (power), K6 VCCIO6 (power), K11 VCCIO3 (power), L4 VCCJ (power), L6 VCC (power), L7 VCCIO5 (power), L8 VCCIO5 (power), L9 VCCIO4 (power), L10 VCCIO4 (power), L11 VCC (power), M5 VCC (power), M9 VCC (power), M12 VCC (power), R2 VCCAUX (power)
part K pins: A1 GND (power), A16 GND (power), G7 GND (power), G8 GND (power), G9 GND (power), G10 GND (power), H7 GND (power), H8 GND (power), H9 GND (power), H10 GND (power), J7 GND (power), J8 GND (power), J9 GND (power), J10 GND (power), K7 GND (power), K8 GND (power), K9 GND (power), K10 GND (power), T1 GND (power), T16 GND (power)
part L pins: B13 NC, C13 NC, E15 NC, E16 NC, F1 NC, F2 NC, F15 NC, F16 NC, G1 NC, G2 NC, G5 NC, G14 NC, G15 NC, G16 NC, H1 NC, H2 NC, H3 NC, H4 NC, H5 NC, H13 NC, H14 NC, H15 NC, H16 NC, J1 NC, J2 NC, J3 NC, J4 NC, J5 NC, J12 NC, J13 NC, J14 NC, J15 NC, K5 NC, K12 NC, R12 NC

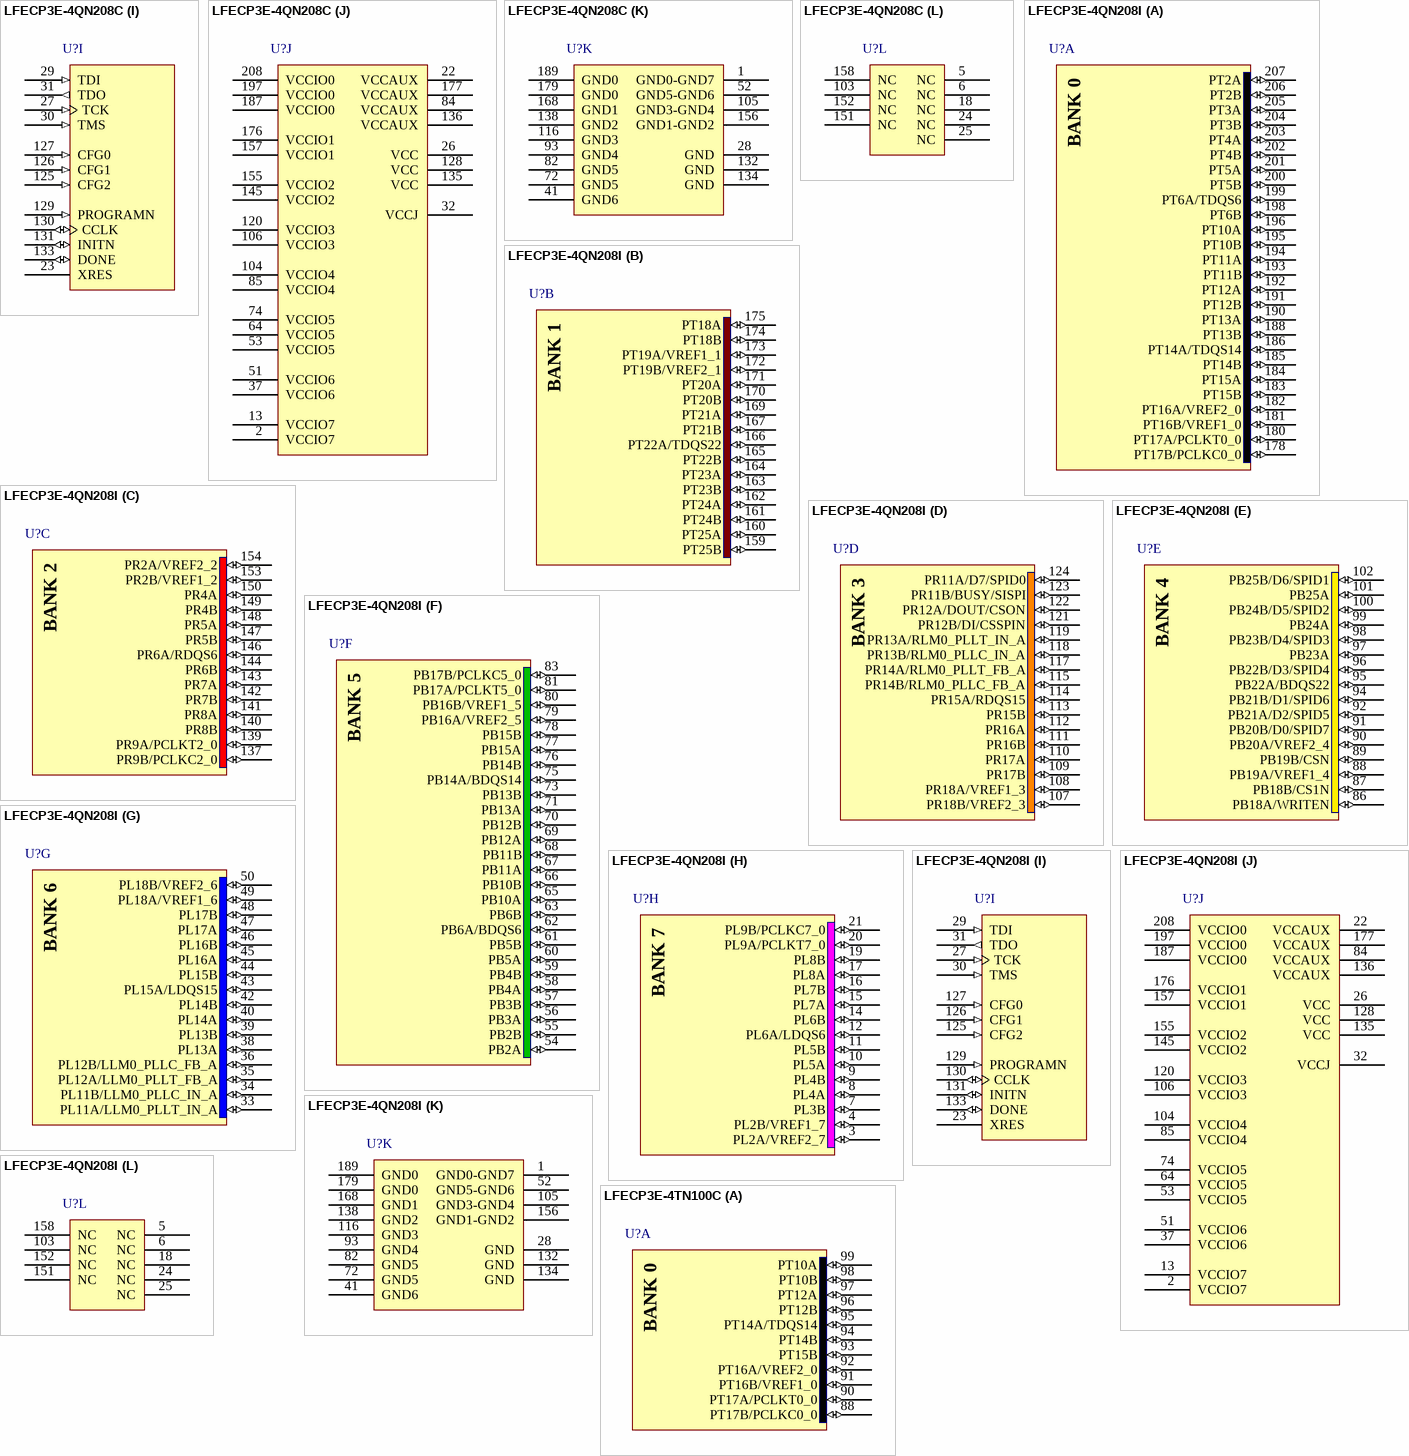
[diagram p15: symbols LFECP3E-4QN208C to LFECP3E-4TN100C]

## LFECP3E-4QN208C
designator U?
ECP 1.2V FPGA, 145 I/Os, 2 PLLs, 3.1K LUTs, 208-Pin PQFP, Pb-Free, Speed Grade 4, Commercial Temperature Grade; Note: Pins 1, 52, 105 and 156 are double bonded.; ComponentAvailability: Not Available
footprint PQFP208_N (Shrink QFP, 208-Leads, Body 28x28mm, Pitch 0.5mm, IPC Medium Density)
footprint PQFP208_L (Shrink QFP, 208-Leads, Body 28x28mm, Pitch 0.5mm, IPC High Density)
footprint PQFP208_M (Shrink QFP, 208-Leads, Body 28x28mm, Pitch 0.5mm, IPC Low Density)
3D model ECP3E-PQFP-208 (208-Pin Plastic Quad Flat Pack (PQFP208))
part A pins: 178 PT17B/PCLKC0_0 (io), 180 PT17A/PCLKT0_0 (io), 181 PT16B/VREF1_0 (io), 182 PT16A/VREF2_0 (io), 183 PT15B (io), 184 PT15A (io), 185 PT14B (io), 186 PT14A/TDQS14 (io), 188 PT13B (io), 190 PT13A (io), 191 PT12B (io), 192 PT12A (io), 193 PT11B (io), 194 PT11A (io), 195 PT10B (io), 196 PT10A (io), 198 PT6B (io), 199 PT6A/TDQS6 (io), 200 PT5B (io), 201 PT5A (io), 202 PT4B (io), 203 PT4A (io), 204 PT3B (io), 205 PT3A (io), 206 PT2B (io), 207 PT2A (io)
part B pins: 159 PT25B (io), 160 PT25A (io), 161 PT24B (io), 162 PT24A (io), 163 PT23B (io), 164 PT23A (io), 165 PT22B (io), 166 PT22A/TDQS22 (io), 167 PT21B (io), 169 PT21A (io), 170 PT20B (io), 171 PT20A (io), 172 PT19B/VREF2_1 (io), 173 PT19A/VREF1_1 (io), 174 PT18B (io), 175 PT18A (io)
part C pins: 137 PR9B/PCLKC2_0 (io), 139 PR9A/PCLKT2_0 (io), 140 PR8B (io), 141 PR8A (io), 142 PR7B (io), 143 PR7A (io), 144 PR6B (io), 146 PR6A/RDQS6 (io), 147 PR5B (io), 148 PR5A (io), 149 PR4B (io), 150 PR4A (io), 153 PR2B/VREF1_2 (io), 154 PR2A/VREF2_2 (io)
part D pins: 107 PR18B/VREF2_3 (io), 108 PR18A/VREF1_3 (io), 109 PR17B (io), 110 PR17A (io), 111 PR16B (io), 112 PR16A (io), 113 PR15B (io), 114 PR15A/RDQS15 (io), 115 PR14B/RLM0_PLLC_FB_A (io), 117 PR14A/RLM0_PLLT_FB_A (io), 118 PR13B/RLM0_PLLC_IN_A (io), 119 PR13A/RLM0_PLLT_IN_A (io), 121 PR12B/DI/CSSPIN (io), 122 PR12A/DOUT/CSON (io), 123 PR11B/BUSY/SISPI (io), 124 PR11A/D7/SPID0 (io)
part E pins: 86 PB18A/WRITEN (io), 87 PB18B/CS1N (io), 88 PB19A/VREF1_4 (io), 89 PB19B/CSN (io), 90 PB20A/VREF2_4 (io), 91 PB20B/D0/SPID7 (io), 92 PB21A/D2/SPID5 (io), 94 PB21B/D1/SPID6 (io), 95 PB22A/BDQS22 (io), 96 PB22B/D3/SPID4 (io), 97 PB23A (io), 98 PB23B/D4/SPID3 (io), 99 PB24A (io), 100 PB24B/D5/SPID2 (io), 101 PB25A (io), 102 PB25B/D6/SPID1 (io)
part F pins: 54 PB2A (io), 55 PB2B (io), 56 PB3A (io), 57 PB3B (io), 58 PB4A (io), 59 PB4B (io), 60 PB5A (io), 61 PB5B (io), 62 PB6A/BDQS6 (io), 63 PB6B (io), 65 PB10A (io), 66 PB10B (io), 67 PB11A (io), 68 PB11B (io), 69 PB12A (io), 70 PB12B (io), 71 PB13A (io), 73 PB13B (io), 75 PB14A/BDQS14 (io), 76 PB14B (io), 77 PB15A (io), 78 PB15B (io), 79 PB16A/VREF2_5 (io), 80 PB16B/VREF1_5 (io), 81 PB17A/PCLKT5_0 (io), 83 PB17B/PCLKC5_0 (io)
part G pins: 33 PL11A/LLM0_PLLT_IN_A (io), 34 PL11B/LLM0_PLLC_IN_A (io), 35 PL12A/LLM0_PLLT_FB_A (io), 36 PL12B/LLM0_PLLC_FB_A (io), 38 PL13A (io), 39 PL13B (io), 40 PL14A (io), 42 PL14B (io), 43 PL15A/LDQS15 (io), 44 PL15B (io), 45 PL16A (io), 46 PL16B (io), 47 PL17A (io), 48 PL17B (io), 49 PL18A/VREF1_6 (io), 50 PL18B/VREF2_6 (io)
part H pins: 3 PL2A/VREF2_7 (io), 4 PL2B/VREF1_7 (io), 7 PL3B (io), 8 PL4A (io), 9 PL4B (io), 10 PL5A (io), 11 PL5B (io), 12 PL6A/LDQS6 (io), 14 PL6B (io), 15 PL7A (io), 16 PL7B (io), 17 PL8A (io), 19 PL8B (io), 20 PL9A/PCLKT7_0 (io), 21 PL9B/PCLKC7_0 (io)
part I pins: 23 XRES, 27 TCK (in), 29 TDI (in), 30 TMS (in), 31 TDO (out), 125 CFG2 (in), 126 CFG1 (in), 127 CFG0 (in), 129 PROGRAMN (in), 130 CCLK (io), 131 INITN (io), 133 DONE (io)
part J pins: 2 VCCIO7 (power), 13 VCCIO7 (power), 22 VCCAUX (power), 26 VCC (power), 32 VCCJ (power), 37 VCCIO6 (power), 51 VCCIO6 (power), 53 VCCIO5 (power), 64 VCCIO5 (power), 74 VCCIO5 (power), 84 VCCAUX (power), 85 VCCIO4 (power), 104 VCCIO4 (power), 106 VCCIO3 (power), 120 VCCIO3 (power), 128 VCC (power), 135 VCC (power), 136 VCCAUX (power), 145 VCCIO2 (power), 155 VCCIO2 (power), 157 VCCIO1 (power), 176 VCCIO1 (power), 177 VCCAUX (power), 187 VCCIO0 (power), 197 VCCIO0 (power), 208 VCCIO0 (power)
part K pins: 1 GND0-GND7 (power), 28 GND (power), 41 GND6 (power), 52 GND5-GND6 (power), 72 GND5 (power), 82 GND5 (power), 93 GND4 (power), 105 GND3-GND4 (power), 116 GND3 (power), 132 GND (power), 134 GND (power), 138 GND2 (power), 156 GND1-GND2 (power), 168 GND1 (power), 179 GND0 (power), 189 GND0 (power)
part L pins: 5 NC, 6 NC, 18 NC, 24 NC, 25 NC, 103 NC, 151 NC, 152 NC, 158 NC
